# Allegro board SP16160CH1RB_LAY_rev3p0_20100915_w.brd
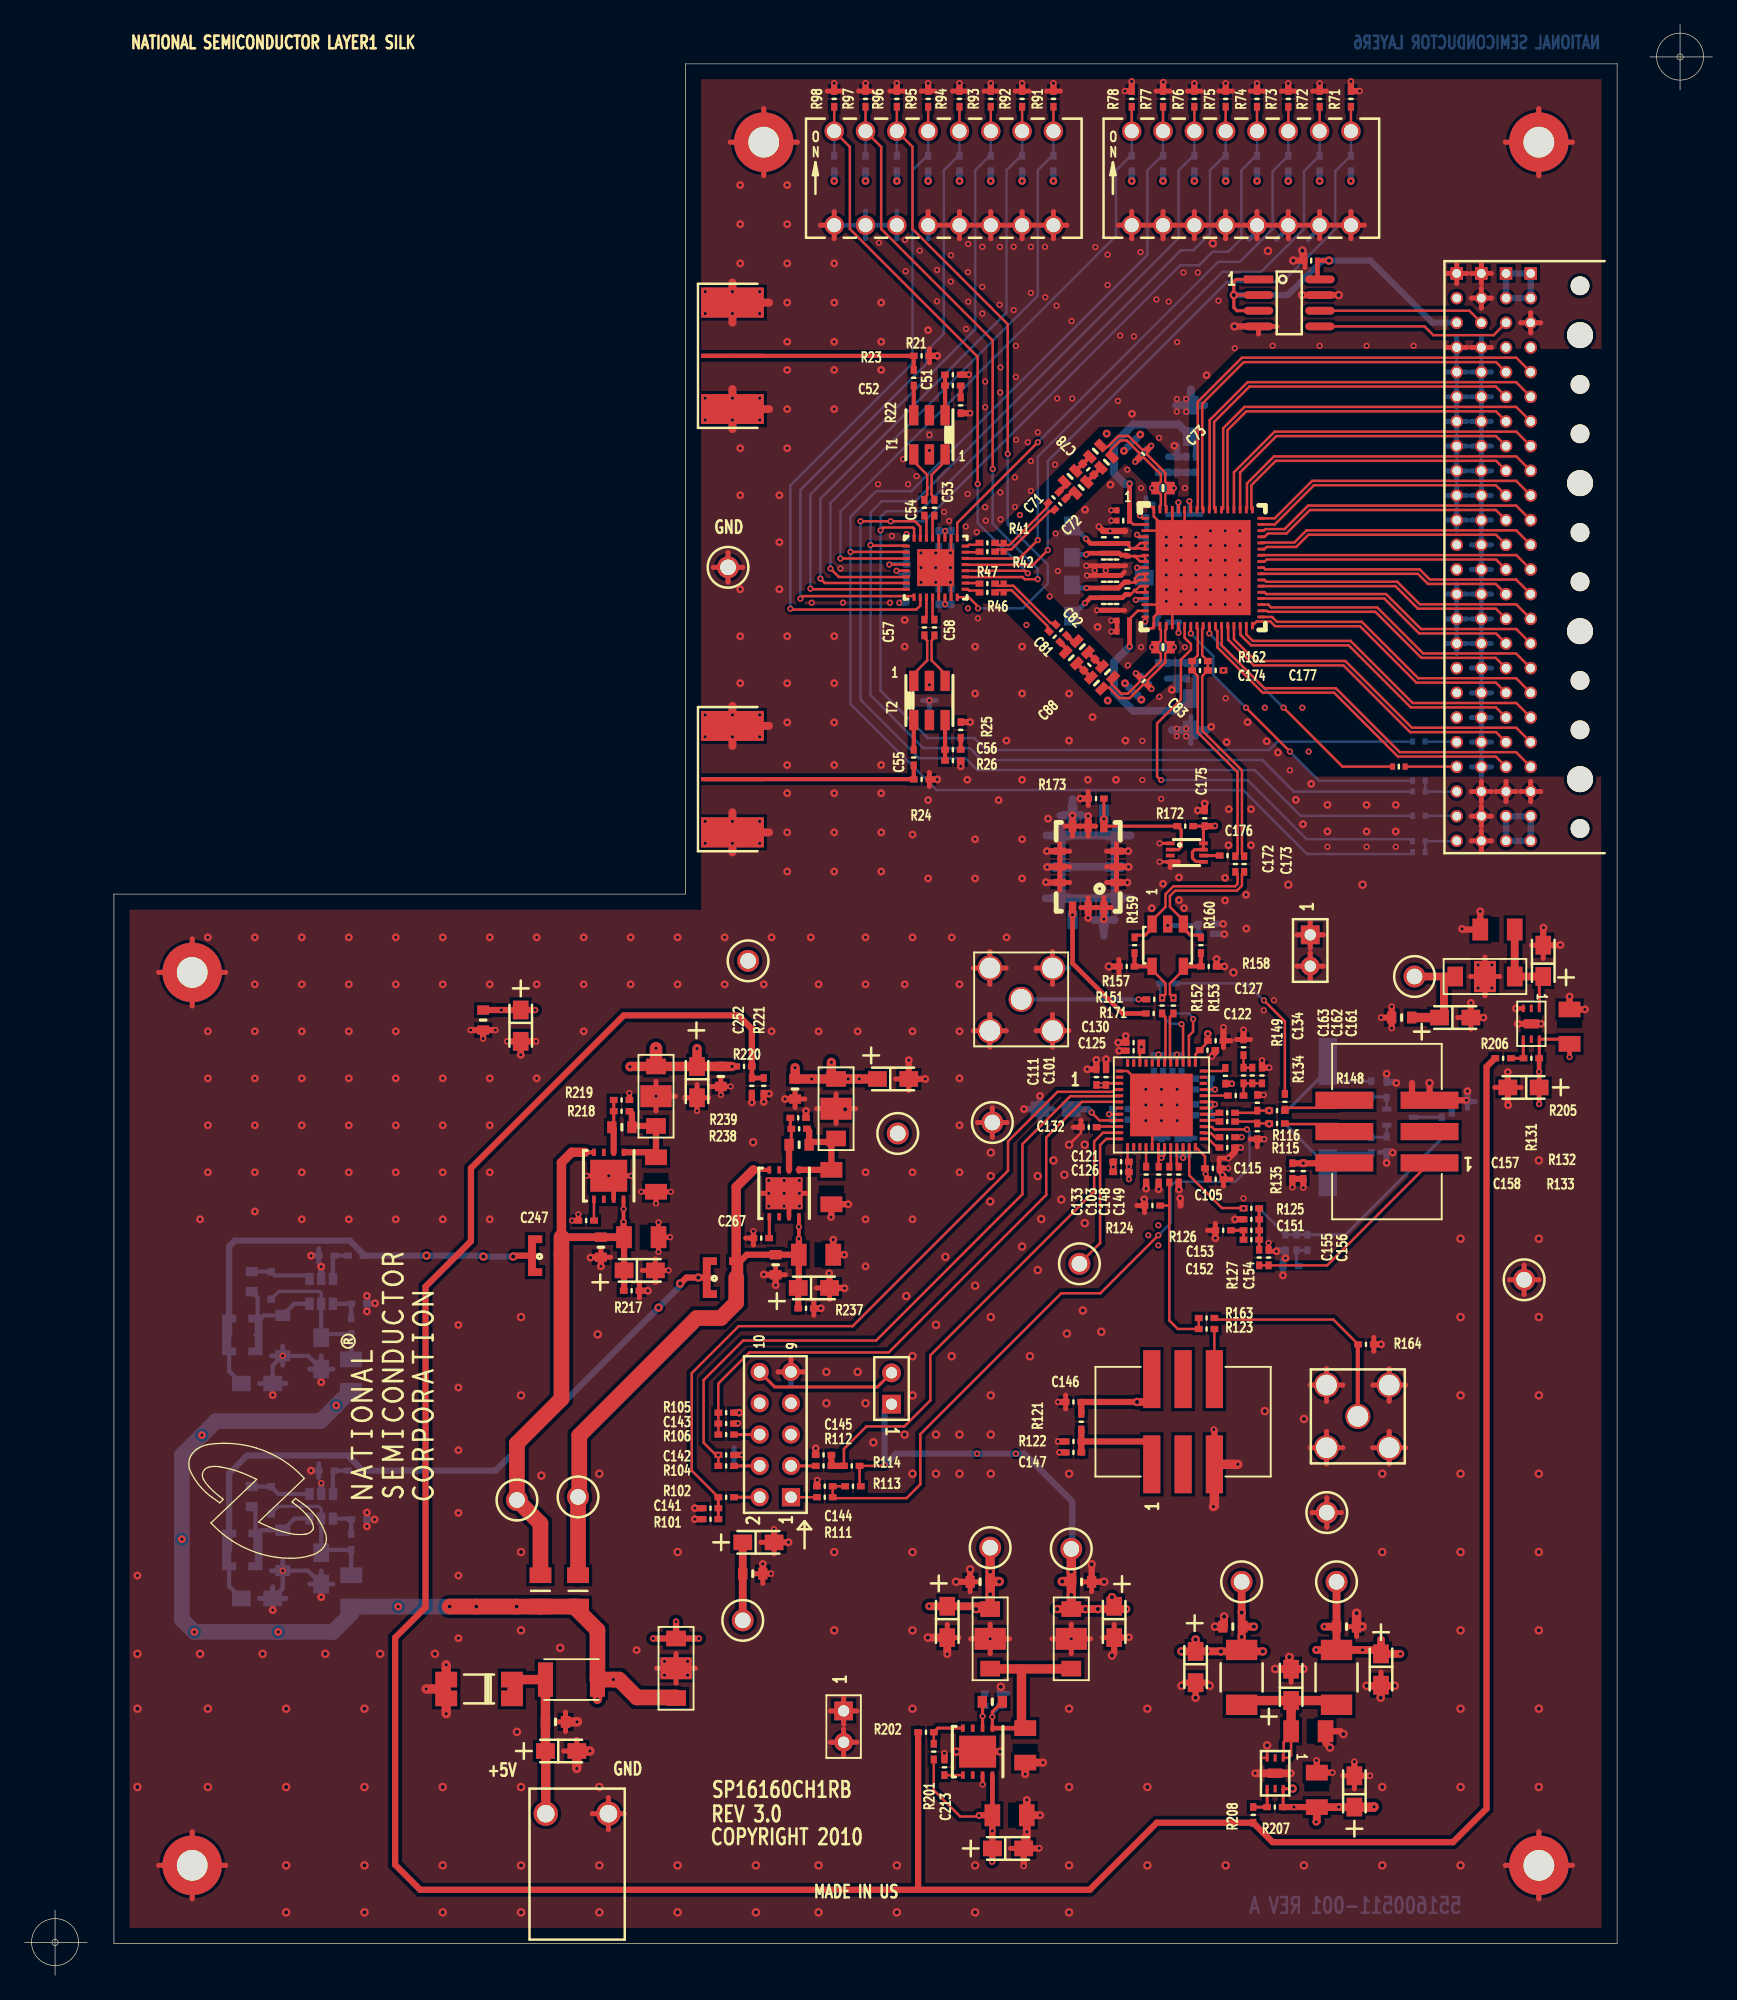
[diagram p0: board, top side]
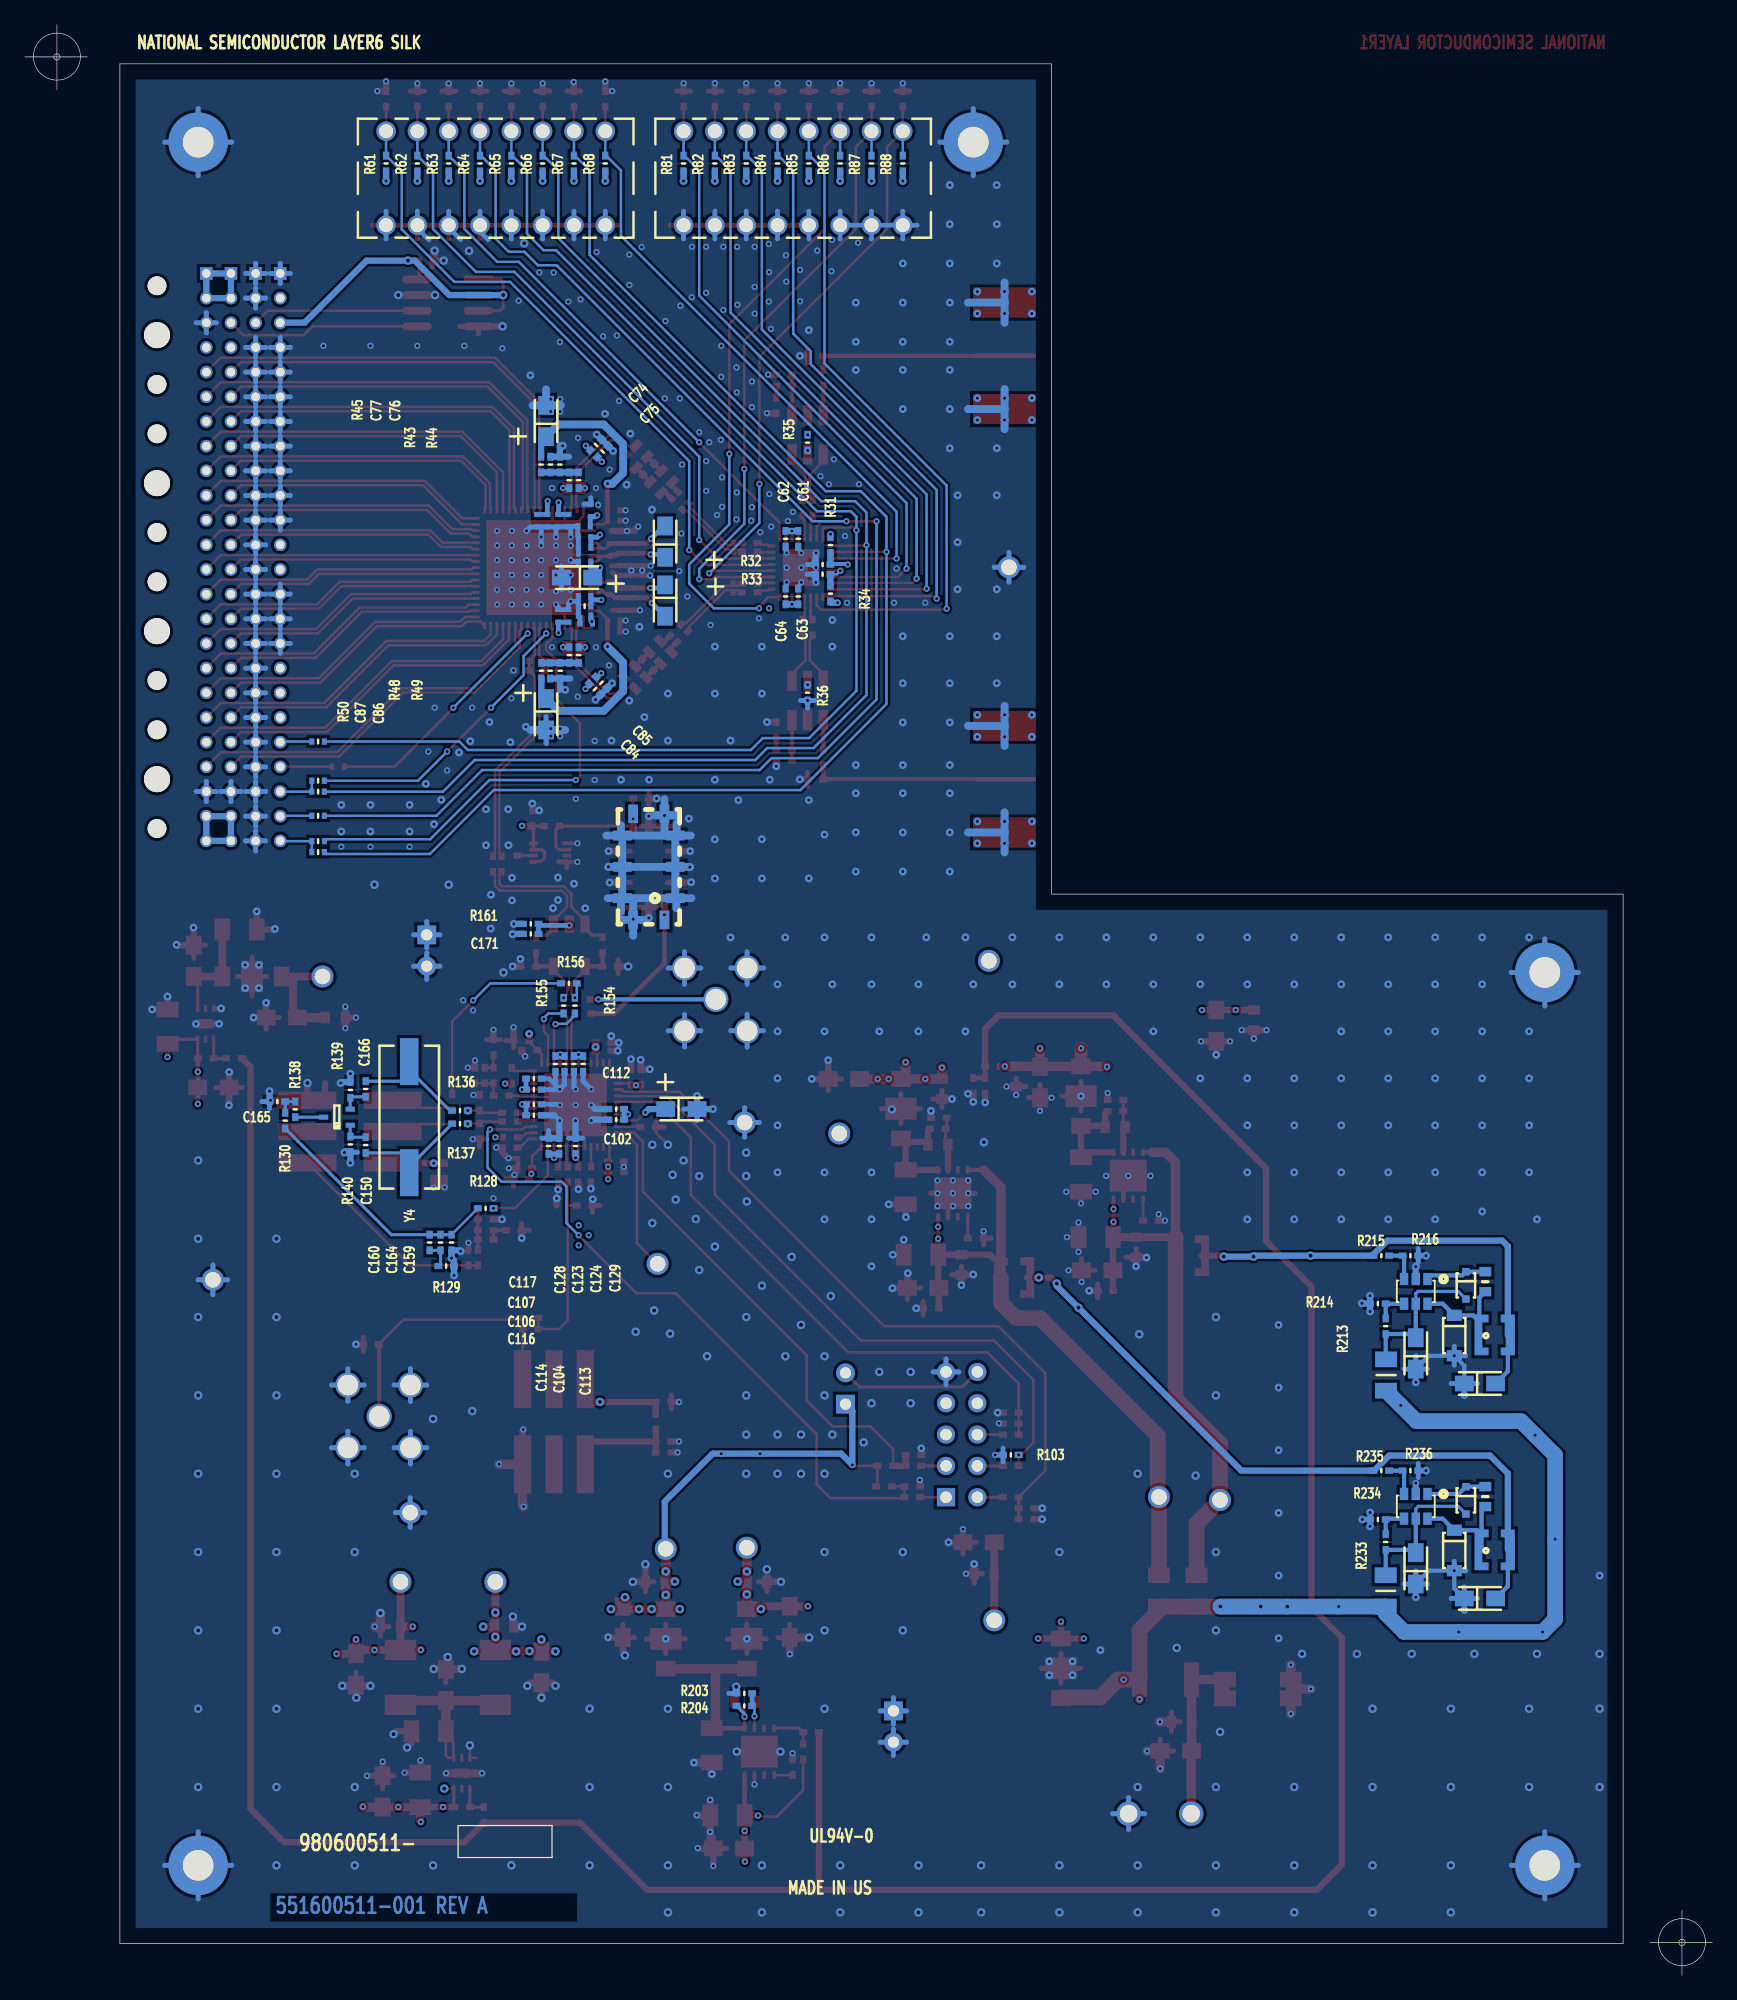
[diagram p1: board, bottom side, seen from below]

Outline 136.88 x 158.14 mm; copper layers: TOP, GROUND_L2, GROUND_L3, POWER_L4, GROUND_L5, BOTTOM. Coordinates in mm from the lower left corner of the outline.
Outline path: 7.24,87.66 53.59,87.66 53.59,154.97 129.16,154.97 129.16,2.57 7.24,2.57 7.24,87.66

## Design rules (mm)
net group DIFF_PAIRS: nets N17069969

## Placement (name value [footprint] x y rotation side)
C1  0.1u  [C0201_NO_SS]  90.04 115.37 90 top
C2  0.1u  [C0402_NO_SS#2]  89.43 115.57 90 top
C3  10u  [SMD_SIZE3216]  84.94 116.23 90 bottom
C4  0.1u  [C0402_NO_SS#2]  88.54 114.78 270 top
C5  0.1u  [C0402_NO_SS#2]  87.53 116.59 90 top
C6  0.1u  [C0402_NO_SS#2]  88.04 114.78 270 top
C7  0.1u  [C0402_NO_SS#2]  88.54 116.59 90 top
C8  0.1u  [C0402_NO_SS#2]  87.53 114.78 270 top
C9  0.1u  [C0402_NO_SS#2]  88.04 116.59 90 top
C11  0.1u  [C0201_NO_SS]  90.04 112.6 270 top
C12  0.1u  [C0402_NO_SS#2]  89.43 112.45 270 top
C13  10u  [SMD_SIZE3216]  84.94 111.46 270 bottom
C14  0.1u  [C0402_NO_SS#2]  88.54 112.98 90 top
C15  0.1u  [C0402_NO_SS#2]  88.54 111.18 270 top
C16  0.1u  [C0402_NO_SS#2]  87.53 112.98 90 top
C17  0.1u  [C0402_NO_SS#2]  88.04 111.18 270 top
C18  0.1u  [C0402_NO_SS#2]  88.04 112.98 90 top
C19  0.1u  [C0402_NO_SS#2]  87.53 111.18 270 top
C21  0.01u  [C0402_NO_SS#2]  91.47 116.59 0 bottom
C22  0.1u  [C0402_NO_SS#2]  91.47 115.75 0 bottom
C23  0.01u  [C0402_NO_SS#2]  90.96 118.77 90 bottom
C24  0.1u  [C0402_NO_SS#2]  91.52 117.47 0 bottom
C25  0.01u  [C0402_NO_SS#2]  91.47 111.81 180 bottom
C26  0.1u  [C0402_NO_SS#2]  91.47 111 180 bottom
C27  0.01u  [C0402_NO_SS#2]  91.47 110.24 180 bottom
C28  0.1u  [C0402_NO_SS#2]  91.34 109.6 180 bottom
C29  10u  [SMD_SIZE3216]  92.08 113.31 0 bottom
C30  0.1u  [C0402_NO_SS#2]  91.47 114.6 0 bottom
C31  0.01u  [C0402_NO_SS#2]  94.49 117.93 270 bottom
C32  0.1u  [C0402_NO_SS#2]  95.33 117.93 270 bottom
C33  0.01u  [C0402_NO_SS#2]  93.6 117.93 270 bottom
C34  0.1u  [C0402_NO_SS#2]  92.79 117.93 270 bottom
C35  0.01u  [C0402_NO_SS#2]  93.6 110.21 90 bottom
C36  0.1u  [C0402_NO_SS#2]  92.79 110.21 90 bottom
C39  0.1u  [C0402_NO_SS#2]  104.34 139.01 180 top
C41  0.1u  [C0402_NO_SS#2]  89.1 117.93 0 top
C42  0.1u  [C0402_NO_SS#2]  89.1 118.77 0 top
C43  10u  [SMD_SIZE3216]  94.59 126.01 90 bottom
C44  0.1u  [C0402_NO_SS#2]  89.1 109.83 0 top
C45  0.1u  [C0402_NO_SS#2]  89.1 108.94 0 top
C46  10u  [SMD_SIZE3216]  94.59 102.23 270 bottom
C51  0.1u  [SMD_SIZE0402]  72.11 129.51 270 top
C52  0.1u  [SMD_SIZE0402]  75.29 128.88 180 top
C53  0.1u  [SMD_SIZE0402]  73.79 118.97 270 top
C54  0.1u  [SMD_SIZE0402]  72.97 118.97 270 top
C55  0.1u  [SMD_SIZE0402]  72.11 98.73 90 top
C56  0.1u  [SMD_SIZE0402]  75.29 99.36 180 top
C57  0.1u  [SMD_SIZE0402]  72.97 109.27 90 top
C58  0.1u  [SMD_SIZE0402]  73.79 109.27 90 top
C61  0.1u  [SMD_SIZE0402]  74.14 116.46 270 bottom
C62  0.01u  [SMD_SIZE0402]  75.16 116.46 270 bottom
C63  0.1u  [SMD_SIZE0402]  74.14 111.79 90 bottom
C64  0.01u  [SMD_SIZE0402]  75.16 111.79 90 bottom
C71  0.1u  [SMD_SIZE0402]  83.44 119.81 45 top
C72  0.1u  [SMD_SIZE0402]  83.98 119.28 45 top
C73  16p  [SMD_SIZE0402]  90.72 123.35 225 top
C74  4p  [SMD_SIZE0402]  90.54 124.07 135 bottom
C75  4p  [SMD_SIZE0402]  90 123.53 315 bottom
C76  0.01u  [SMD_SIZE0402]  93.47 122.48 90 bottom
C77  0.1u  [SMD_SIZE0402]  94.23 122.48 90 bottom
C78  4p  [SMD_SIZE0402]  86.26 122.1 315 top
C79  3p  [C0402_NO_SS]  79.4 115.77 270 top
C80  3p  [C0402_NO_SS]  79.4 112.47 90 top
C81  0.1u  [SMD_SIZE0402]  83.53 108.52 315 top
C82  0.1u  [SMD_SIZE0402]  84.07 109.06 315 top
C83  16p  [SMD_SIZE0402]  90.76 104.93 135 top
C84  4p  [SMD_SIZE0402]  90.63 104.26 225 bottom
C85  4p  [SMD_SIZE0402]  90.09 104.8 45 bottom
C86  0.01u  [SMD_SIZE0402]  93.45 105.77 270 bottom
C87  0.1u  [SMD_SIZE0402]  94.26 105.77 270 bottom
C88  4p  [SMD_SIZE0402]  86.35 106.24 45 top
C101  100p  [SMD_SIZE0402]  87.71 72.82 270 top
C102  100p  [SMD_SIZE0402]  88.9 69.37 180 bottom
C103  100p  [SMD_SIZE0402]  91.97 64.92 90 top
C104  100p  [SMD_SIZE0402]  93.52 67.23 270 bottom
C105  100p  [SMD_SIZE0402]  96.6 64.54 180 top
C106  100p  [SMD_SIZE0402]  95.58 70.61 0 bottom
C107  100p  [SMD_SIZE0402]  95.58 71.81 0 bottom
C111  0.1u  [SMD_SIZE0402]  86.92 72.82 270 top
C112  0.1u  [SMD_SIZE0402]  88.9 70.23 180 bottom
C113  0.1u  [SMD_SIZE0402]  92.2 67.23 270 bottom
C114  0.1u  [SMD_SIZE0402]  94.39 67.23 270 bottom
C115  0.1u  [SMD_SIZE0402]  96.37 65.43 180 top
C116  0.1u  [SMD_SIZE0402]  95.58 69.72 0 bottom
C117  0.1u  [SMD_SIZE0402]  95.58 72.69 0 bottom
C121  100p  [SMD_SIZE0402]  88.93 65.96 0 top
C122  100p  [SMD_SIZE0402]  95.94 75.01 180 top
C123  100p  [SMD_SIZE0402]  93.09 73.89 90 bottom
C124  100p  [SMD_SIZE0402]  92.33 73.89 90 bottom
C125  100p  [SMD_SIZE0402]  89.94 74.96 0 top
C126  0.1u  [SMD_SIZE0402]  88.93 65.13 0 top
C127  0.1u  [SMD_SIZE0402]  96.6 75.77 180 top
C128  0.1u  [SMD_SIZE0402]  93.83 73.89 90 bottom
C129  0.1u  [SMD_SIZE0402]  91.59 73.89 90 bottom
C130  0.1u  [SMD_SIZE0402]  89.94 75.62 0 top
C131  10u  [SMD_SIZE3216]  83.62 70.23 180 bottom
C132  0.1u  [SMD_SIZE0402]  86.31 68.76 0 top
C133  1u  [SMD_SIZE0402]  90.96 64.92 90 top
C134  1u  [SMD_SIZE0402]  97.38 72.92 270 top
C141  A/R  [SMD_SIZE0402]  55.63 37.87 0 top
C142  A/R  [SMD_SIZE0402]  56.9 42.19 180 top
C143  A/R  [SMD_SIZE0402]  56.9 44.73 180 top
C144  100p  [SMD_SIZE0402]  64.9 39.65 0 top
C145  0.1u  [SMD_SIZE0402]  64.8 42.19 0 top
C146  0.01u  [SMD_SIZE0402]  85.06 46.48 0 top
C147  A/R  [SMD_SIZE0402]  85.06 42.39 0 top
C148  0.1u  [SMD_SIZE0402]  92.84 64.92 90 top
C149  0.1u  [SMD_SIZE0402]  93.6 64.92 90 top
C150  A/R  [SMD_SIZE0402]  109.22 67.31 270 bottom
C151  0.1u  [SMD_SIZE0402]  99.49 61.29 0 top
C152  0.68u  [SMD_SIZE0402]  99.49 59.64 0 top
C153  A/R  [SMD_SIZE0402]  99.49 60.4 0 top
C154  A/R  [SMD_SIZE0402]  100.89 58.19 270 top
C155  0.1u  [SMD_SIZE0402]  102.82 65.2 90 top
C156  100p  [SMD_SIZE0402]  103.71 65.2 90 top
C157  0.1u  [SMD_SIZE0402]  97.54 69.93 0 top
C158  0.1u  [SMD_SIZE0402]  97.54 69.22 0 top
C159  A/R  [SMD_SIZE0402]  102.26 59.41 90 bottom
C160  A/R  [SMD_SIZE0402]  104.04 59.41 90 bottom
C161  A/R  [SMD_SIZE0402]  100.36 72.95 270 top
C162  A/R  [SMD_SIZE0402]  99.57 72.95 270 top
C163  12n  [SMD_SIZE0402]  98.86 72.95 270 top
C164  A/R  [SMD_SIZE0402]  103.15 59.41 90 bottom
C165  A/R  [SMD_SIZE0402]  116.38 70.84 180 bottom
C166  A/R  [SMD_SIZE0402]  109.22 71.86 90 bottom
C171  A/R  [SMD_SIZE0402]  95.83 84.43 180 bottom
C172  A/R  [SMD_SIZE0402]  98.2 90.09 270 top
C173  A/R  [SMD_SIZE0402]  98.91 90.09 270 top
C174  10p  [SMD_SIZE0402]  95.33 105.79 0 top
C175  0.1u  [SMD_SIZE0402]  95.71 93.8 90 top
C176  20p  [SMD_SIZE0402]  97.56 90.78 180 top
C177  0.1u  [SMD_SIZE0402]  96.6 105.79 0 top
C201  10u  [SMD_SIZE3216]  43.51 18.19 0 top
C202  0.1u  [SMD_SIZE0603]  43.05 20.55 0 top
C203  10u  [SMD_SIZE3216]  40.23 76.99 270 top
C204  0.1u  [SMD_SIZE0603]  37.19 77.44 270 top
C205  10u  [SMD_SIZE3216]  59.51 35.1 0 top
C206  0.1u  [SMD_SIZE0603]  59.05 32.56 0 top
C211  10u  [SMD_SIZE3216]  79.76 10.29 0 top
C212  1u  [SMD_SIZE1206]  78.87 12.98 0 top
C213  0.01u  [SMD_SIZE0402]  74.6 16.87 90 top
C214  2.2n  [SMD_SIZE0603]  78.49 22.17 180 top
C215  10u  [SMD_SIZE1206]  81.15 19.66 270 top
C216  10u  [SMD_SIZE3216]  88.37 28.65 270 top
C217  0.1u  [SMD_SIZE0603]  85.73 31.9 0 top
C218  10u  [SMD_SIZE3216]  74.83 28.65 270 top
C219  0.1u  [SMD_SIZE0603]  77.5 31.9 180 top
C221  10u  [SMD_SIZE3216]  121.56 71.98 180 top
C222  1u  [SMD_SIZE1206]  125.3 75.9 90 top
C223  10u  [SMD_SIZE3216]  123.16 82.25 90 top
C224  1u  [SMD_SIZE1206]  120.47 84.79 180 top
C225  10u  [SMD_SIZE3216]  116.03 77.65 0 top
C226  0.1u  [SMD_SIZE0603]  111.68 77.65 180 top
C231  10u  [SMD_SIZE3216]  107.85 14.91 90 top
C232  1u  [SMD_SIZE1206]  104.8 14.02 90 top
C233  10u  [SMD_SIZE3216]  102.72 23.55 90 top
C234  1u  [SMD_SIZE1206]  103.1 19.79 0 top
C235  10u  [SMD_SIZE3216]  94.97 24.99 270 top
C236  0.1u  [SMD_SIZE0603]  97.99 28.27 180 top
C237  10u  [SMD_SIZE3216]  110.01 24.79 270 top
C238  0.1u  [SMD_SIZE0603]  107.21 28.27 0 top
C241  10u  [SMD_SIZE3216]  24.05 50.42 90 bottom
C242  0.01u  [SMD_SIZE0603]  18.41 56.24 270 bottom
C243  10u  [SMD_SIZE3216]  18.85 47.98 180 bottom
C244  A/R  [SMD_SIZE0603]  46.74 59.03 90 top
C245  10u  [SMD_SIZE3216]  49.89 57.15 0 top
C246  1u  [SMD_SIZE1206]  49 59.84 0 top
C247  0.01u  [SMD_SIZE0402]  45.54 61.19 180 top
C248  2.2n  [SMD_SIZE0603]  48.44 68.76 180 top
C249  10u  [SMD_SIZE1206]  51.21 65.94 270 top
C250  10u  [SMD_SIZE3216]  54.53 72.42 270 top
C251  0.1u  [SMD_SIZE0603]  56.46 72.87 270 top
C252  0.1u  [SMD_SIZE0402]  58.98 72.11 270 top
C261  10u  [SMD_SIZE3216]  24.05 32.99 90 bottom
C262  0.01u  [SMD_SIZE0603]  18.41 38.81 270 bottom
C263  10u  [SMD_SIZE3216]  18.85 30.56 180 bottom
C264  A/R  [SMD_SIZE0603]  60.91 57.61 90 top
C265  10u  [SMD_SIZE3216]  64.01 55.73 0 top
C266  1u  [SMD_SIZE1206]  63.17 58.42 0 top
C267  0.01u  [SMD_SIZE0402]  59.74 59.77 180 top
C268  2.2n  [SMD_SIZE0603]  62.81 67.34 180 top
C269  10u  [SMD_SIZE1206]  65.43 64.92 270 top
C270  10u  [SMD_SIZE3216]  70.43 72.67 0 top
C271  0.1u  [SMD_SIZE0603]  62.48 71.86 270 top
D1  1N5818M  [MELF-MLL41]  36.86 23.22 180 top
D2  BAT54WS  [SOD323]  19.99 55.93 270 bottom
D3  MBR0530  [SOD_123]  20.93 51.87 270 bottom
D4  BAT54WS  [SOD323]  19.99 38.51 270 bottom
D5  MBR0530  [SOD_123]  20.93 34.44 270 bottom
D6  SMV1249-074  [SC70_3]  111.56 69.57 0 bottom
H3  HDR2x5  [BLKCON_5X2]  60.88 43.84 180 top
H4  4 - 6x4 FutureBus Connector  [FBUS_RS_96_ECL]  122.15 137.97 0 top
JP1  HDR-1x2  [BLKCON_2X1]  70.31 47.57 180 top
JP10  HDR-1x2  [BLKCON_2X1]  66.42 20.17 0 top
JP11  HDR-1x2  [BLKCON_2X1]  104.27 83.08 0 top
L1  110n  [0603CS]  84.79 121.52 45 top
L2  110n  [0603CS]  85.69 120.62 45 top
L3  33n  [0603CS]  92.33 120.57 0 top
L4  110n  [0603CS]  84.88 106.81 315 top
L5  110n  [0603CS]  85.78 107.71 315 top
L6  33n  [0603CS]  92.33 107.67 0 top
L7  200n  [0603CS]  87.74 122.67 45 top
L8  200n  [0603CS]  87.83 105.66 315 top
L9  200n  [0603CS]  86.93 104.77 315 top
L10  200n  [0603CS]  86.84 123.57 45 top
L11  EXC-CL4532U1  [L4532]  44.35 23.98 0 top
L12  100u  [SMD_SIZE1812R]  98.7 24.16 90 top
L13  100u  [SMD_SIZE1812R]  106.4 24.16 90 top
L21  4.6u  [LPS3008_472ML]  17.65 50.27 180 bottom
L22  0 ohm  [LPS3008_472ML]  42.47 56.69 0 top
L23  4.6u  [LPS3008_472ML]  17.65 32.84 180 bottom
L24  0 ohm  [LPS3008_472ML]  56.64 54.91 0 top
MH1  M-Hole  [MOUNTING_HOLE]  59.94 148.62 0 top
MH2  M-Hole  [MOUNTING_HOLE]  122.81 148.62 0 top
MH3  M-Hole  [MOUNTING_HOLE]  13.59 8.92 0 top
MH4  M-Hole  [MOUNTING_HOLE]  122.81 8.92 0 top
MH5  M-Hole  [MOUNTING_HOLE]  13.59 81.31 0 top
NOREF  -  []  -131.22 -104.9 0 top
NOREF#2  -  []  -2.62 2.64 0 top
NOREF#3  -  []  -29.59 -126.97 0 top
NOREF#4  -  []  220.14 -17.25 0 top
NOREF#5  -  []  129.18 155.5 0 top
NOREF#6  -  []  15.49 46.86 90 top
NOREF#7  -  []  53.59 87.66 90 top
NOREF#8  -  []  7.24 2.57 90 top
NOREF#9  -  []  7.24 2.57 0 top
POWER  Terminal_Block2  [MSTBA_RA_200_2]  44.81 13.11 90 top
R1  10  [C0402_NO_SS#2]  111.46 97.99 0 top
R2  10  [C0402_NO_SS#2]  113.08 96.85 0 bottom
R3  10  [C0402_NO_SS#2]  113.08 91.95 0 bottom
R4  10  [C0402_NO_SS#2]  113.08 91.06 0 bottom
R5  10  [C0402_NO_SS#2]  113.08 95.96 0 bottom
R6  A/R  [C0402_NO_SS#2]  113.08 94.01 0 bottom
R7  10  [C0402_NO_SS#2]  113.08 100.03 0 bottom
R21  A/R  [SMD_SIZE0402]  72.75 131.29 0 top
R22  0  [SMD_SIZE0402]  75.92 127.28 270 top
R23  A/R  [SMD_SIZE0402]  75.29 129.77 0 top
R24  A/R  [SMD_SIZE0402]  72.75 96.95 0 top
R25  0  [SMD_SIZE0402]  75.92 100.97 90 top
R26  A/R  [SMD_SIZE0402]  75.29 98.48 0 top
R31  A/R  [SMD_SIZE0402]  71.53 115.95 90 bottom
R32  0  [SMD_SIZE0402]  72.16 114.38 0 bottom
R33  24k  [SMD_SIZE0402]  72.16 113.59 0 bottom
R34  11k  [SMD_SIZE0402]  71.53 112.01 270 bottom
R35  0  [SMD_SIZE0402]  73.38 124.26 90 bottom
R36  0  [SMD_SIZE0402]  73.38 103.99 270 bottom
R41  10  [SMD_SIZE0402]  78.08 116.13 0 top
R42  10  [SMD_SIZE0402]  78.08 115.42 0 top
R43  100  [SMD_SIZE0402]  92.71 121.21 90 bottom
R44  100  [SMD_SIZE0402]  91.95 121.21 270 bottom
R45  24.9  [SMD_SIZE0402]  95 122.48 90 bottom
R46  10  [SMD_SIZE0402]  78.08 112.12 0 top
R47  10  [SMD_SIZE0402]  78.08 112.83 0 top
R48  100  [SMD_SIZE0402]  92.71 107.04 270 bottom
R49  100  [SMD_SIZE0402]  91.95 107.04 90 bottom
R50  24.9  [SMD_SIZE0402]  94.97 105.77 270 bottom
R61  A/R  [SMD_SIZE0402]  107.57 146.89 90 bottom
R62  A/R  [SMD_SIZE0402]  105.03 146.89 90 bottom
R63  A/R  [SMD_SIZE0402]  102.49 146.89 90 bottom
R64  A/R  [SMD_SIZE0402]  99.95 146.89 90 bottom
R65  A/R  [SMD_SIZE0402]  97.41 146.89 90 bottom
R66  A/R  [SMD_SIZE0402]  94.87 146.89 90 bottom
R67  A/R  [SMD_SIZE0402]  92.33 146.89 90 bottom
R68  A/R  [SMD_SIZE0402]  89.79 146.89 90 bottom
R71  0  [SMD_SIZE0402]  107.57 152.12 90 top
R72  A/R  [SMD_SIZE0402]  105.03 152.12 90 top
R73  0  [SMD_SIZE0402]  102.49 152.12 90 top
R74  A/R  [SMD_SIZE0402]  99.95 152.12 90 top
R75  A/R  [SMD_SIZE0402]  97.41 152.12 90 top
R76  A/R  [SMD_SIZE0402]  94.87 152.12 90 top
R77  A/R  [SMD_SIZE0402]  92.33 152.12 90 top
R78  0  [SMD_SIZE0402]  89.79 152.12 90 top
R81  A/R  [SMD_SIZE0402]  83.44 146.89 90 bottom
R82  A/R  [SMD_SIZE0402]  80.9 146.89 90 bottom
R83  A/R  [SMD_SIZE0402]  78.36 146.89 90 bottom
R84  A/R  [SMD_SIZE0402]  75.82 146.89 90 bottom
R85  A/R  [SMD_SIZE0402]  73.28 146.89 90 bottom
R86  A/R  [SMD_SIZE0402]  70.74 146.89 90 bottom
R87  A/R  [SMD_SIZE0402]  68.2 146.89 90 bottom
R88  A/R  [SMD_SIZE0402]  65.66 146.89 90 bottom
R91  0  [SMD_SIZE0402]  83.44 152.12 90 top
R92  0  [SMD_SIZE0402]  80.9 152.12 90 top
R93  0  [SMD_SIZE0402]  78.36 152.12 90 top
R94  0  [SMD_SIZE0402]  75.82 152.12 90 top
R95  0  [SMD_SIZE0402]  73.28 152.12 90 top
R96  0  [SMD_SIZE0402]  70.74 152.12 90 top
R97  A/R  [SMD_SIZE0402]  68.2 152.12 90 top
R98  0  [SMD_SIZE0402]  65.66 152.12 90 top
R101  24k  [SMD_SIZE0402]  55.63 36.98 180 top
R102  11k  [SMD_SIZE0402]  56.9 38.76 0 top
R103  24k  [SMD_SIZE0402]  56.9 42.19 0 bottom
R104  11k  [SMD_SIZE0402]  56.9 41.3 0 top
R105  24k  [SMD_SIZE0402]  56.9 45.62 0 top
R106  11k  [SMD_SIZE0402]  56.9 43.84 0 top
R111  200  [SMD_SIZE0402]  64.9 38.76 180 top
R112  200  [SMD_SIZE0402]  64.8 41.3 180 top
R113  2.32k  [SMD_SIZE0402]  67.18 39.65 0 top
R114  2.32k  [SMD_SIZE0402]  67.08 41.3 0 top
R115  0  [SMD_SIZE0402]  97.54 67.11 180 top
R116  0  [SMD_SIZE0402]  97.54 67.94 180 top
R121  1k  [SMD_SIZE0402]  85.7 44.88 90 top
R122  A/R  [SMD_SIZE0402]  85.06 43.28 0 top
R123  200  [SMD_SIZE0402]  95.86 52.4 180 top
R124  200  [SMD_SIZE0402]  91.47 62.41 180 top
R125  0  [SMD_SIZE0402]  99.49 62.18 0 top
R126  39k  [SMD_SIZE0402]  97.21 60.4 0 top
R127  0  [SMD_SIZE0402]  100.13 58.19 270 top
R128  A/R  [SMD_SIZE0402]  99.49 62.18 0 bottom
R129  A/R  [SMD_SIZE0402]  102.69 57.51 0 bottom
R130  A/R  [SMD_SIZE0402]  115.75 69.29 90 bottom
R131  A/R  [SMD_SIZE0402]  102.21 70.82 90 top
R132  200  [SMD_SIZE0402]  101.57 70.1 0 top
R133  A/R  [SMD_SIZE0402]  101.57 69.06 0 top
R134  200  [SMD_SIZE0402]  99.97 70.74 90 top
R135  0  [SMD_SIZE0402]  99.97 68.43 90 top
R136  A/R  [SMD_SIZE0402]  101.57 70.1 180 bottom
R137  A/R  [SMD_SIZE0402]  101.57 69.04 180 bottom
R138  A/R  [SMD_SIZE0402]  114.94 70.21 90 bottom
R139  A/R  [SMD_SIZE0402]  110.46 71.78 270 bottom
R140  A/R  [SMD_SIZE0402]  110.46 67.36 270 bottom
R148  0  [SMD_SIZE0402]  98.22 71.32 0 top
R149  1.8k  [SMD_SIZE0402]  98.86 75.23 270 top
R151  A/R  [SMD_SIZE0402]  91.62 79.12 180 top
R152  A/R  [SMD_SIZE0402]  92.25 78.61 270 top
R153  A/R  [SMD_SIZE0402]  93.17 78.61 270 top
R154  A/R  [SMD_SIZE0402]  92.25 78.61 270 bottom
R155  A/R  [SMD_SIZE0402]  93.17 78.61 270 bottom
R156  A/R  [SMD_SIZE0402]  92.74 80.42 180 bottom
R157  A/R  [SMD_SIZE0402]  89.38 81.79 180 top
R158  A/R  [SMD_SIZE0402]  96.04 81.79 180 top
R159  A/R  [SMD_SIZE0402]  90.02 83.52 90 top
R160  A/R  [SMD_SIZE0402]  95.4 83.52 90 top
R161  A/R  [SMD_SIZE0402]  95.83 85.24 180 bottom
R162  A/R  [SMD_SIZE0402]  95.33 106.55 180 top
R163  A/R  [SMD_SIZE0402]  95.86 53.29 180 top
R164  A/R  [SMD_SIZE0402]  108.79 51.16 180 top
R171  49.9  [SMD_SIZE0402]  91.57 77.98 0 top
R172  402  [SMD_SIZE0402]  94.13 93.17 180 top
R173  402  [SMD_SIZE0402]  86.89 95.4 180 top
R201  A/R  [SMD_SIZE0402]  73.74 18.14 90 top
R202  0  [SMD_SIZE0402]  73.1 19.71 0 top
R203  1k  [SMD_SIZE0402]  78.51 22.86 0 bottom
R204  2.32k  [SMD_SIZE0402]  78.51 21.84 0 bottom
R205  A/R  [SMD_SIZE0402]  122.2 74.35 180 top
R206  0  [SMD_SIZE0402]  119.91 74.35 0 top
R207  A/R  [SMD_SIZE0402]  101.4 13.64 180 top
R208  0  [SMD_SIZE0402]  99.64 13 90 top
R211  A/R  [SMD_SIZE0805]  41.83 31.17 90 top
R212  0  [SMD_SIZE0805]  26.47 48.67 90 bottom
R213  100k  [SMD_SIZE0402]  26.49 52.63 90 bottom
R214  A/R  [SMD_SIZE0402]  27.13 54.46 180 bottom
R215  39k  [SMD_SIZE0402]  26.85 58.34 180 bottom
R216  11k  [SMD_SIZE0402]  24.49 58.34 180 bottom
R217  A/R  [SMD_SIZE0402]  49.23 55.5 180 top
R218  2k  [SMD_SIZE0402]  48.41 70.05 0 top
R219  1k  [SMD_SIZE0402]  48.41 70.97 0 top
R220  11k  [SMD_SIZE0402]  58.34 73.69 180 top
R221  24k  [SMD_SIZE0402]  59.94 72.11 90 top
R231  A/R  [SMD_SIZE0805]  44.88 31.17 90 top
R232  0  [SMD_SIZE0805]  26.49 31.17 90 bottom
R233  100k  [SMD_SIZE0402]  26.49 35.13 90 bottom
R234  A/R  [SMD_SIZE0402]  27.13 36.96 180 bottom
R235  24k  [SMD_SIZE0402]  26.85 40.92 180 bottom
R236  11k  [SMD_SIZE0402]  24.49 40.92 180 bottom
R237  A/R  [SMD_SIZE0402]  63.37 54.08 180 top
R238  806  [SMD_SIZE0402]  62.81 68.63 0 top
R239  1k  [SMD_SIZE0402]  62.74 69.52 0 top
SAM_AMP_Q  WM5534  [RF_SMA_END_LAUNCH]  57.4 96.98 0 top
SMA_AMP_I  WM5534  [RF_SMA_END_LAUNCH]  57.4 131.29 0 top
SMA_CLK  A/R  [SMA_V_CLR]  80.82 79.12 0 top
SMA_REF  A/R  [SMA_V_CLR]  108.13 45.31 0 top
SWGI  A/R  [BD08]  91.06 145.69 0 top
SWGQ  A/R  [BD08]  66.93 145.69 0 top
T1  TCM4-19+  [DB714]  73.38 124.89 180 top
T2  TCM4-19+  [DB714]  73.38 103.35 0 top
T4  A/R  [SM_SOT23_5_WGP150]  92.71 83.52 90 top
TP1  GND  [TP_500X_50]  121.62 56.39 0 top
TP2  GND  [TP_500X_50]  57.05 114.15 0 top
TP3  GND  [TP_500X_50]  78.49 69.14 0 top
TP4  GND  [TP_500X_50]  105.61 37.52 0 top
TP5  LD  [TP_500X_50]  85.55 57.68 0 top
TP11  VAMP  [TP_500X_50]  58.24 28.78 180 top
TP12  VPLL  [TP_500X_50]  84.89 34.57 0 top
TP13  VPLLIO  [TP_500X_50]  78.31 34.67 0 top
TP14  VA3P0SW  [TP_500X_50]  39.93 38.53 0 top
TP15  VA3P0  [TP_500X_50]  58.67 82.25 0 top
TP16  VA1P8SW  [TP_500X_50]  44.88 38.79 0 top
TP17  VA1P8  [TP_500X_50]  70.82 68.25 0 top
TP18  VIO1p8  [TP_500X_50]  112.73 80.98 0 top
TP19  VREFOSC  [TP_500X_50]  98.7 31.9 0 top
TP20  VVCXO  [TP_500X_50]  106.4 31.9 0 top
U1  ADC16DV160  [SC-MKT-LQA68A]  95.58 114.12 0 top
U2  24C02/SO8  [SOIC8_050_WG244_L200]  102.57 135.59 0 top
U3  LMH6517  [32LLP_SQA32A]  73.89 114.12 0 top
U4  LMK04021  [LLP48_P5M_7X7_EP]  92.2 70.56 0 top
U5  TSF153F  [TFS153F]  86.26 89.87 90 top
U6  NC7WV125  [NC7WV125_8P]  92.91 91.77 0 top
U11  LM3878SD-ADJ  [SC-MKT-SDC08A_LLP]  77.29 18.14 90 top
U12  LM2734Y  [TSOT-6]  24.05 55.45 270 bottom
U13  LP3878SD-ADJ  [SC-MKT-SDC08A_LLP]  47.37 64.82 90 top
U14  LM2734Y  [TSOT-6]  24.05 38.02 270 bottom
U15  LP3878SD-ADJ  [SC-MKT-SDC08A_LLP]  61.59 63.4 90 top
U16  LP5900SD-1.8  [LLP6_65M_WG2P5_L2P2_EP]  122.2 77.14 270 top
U17  LP5900SD-3.3  [LLP6_65M_WG2P5_L2P2_EP]  101.42 16.38 270 top
U18  TFS 123A  [TFS123A]  86.26 89.87 90 bottom
Y2  OSC 76.8MHz CVHD-950-76.800  [SOIC6_100_WG272_L560]  110.49 68.4 180 top
Y3  OSC 61.44MHz CCHD-950-25-61.440  [SOIC6_100_WG272_L560]  93.95 44.88 90 top
Y4  VXB1-1127-12M288  [VXB1_1127_12M288]  105.69 69.57 270 bottom
Z1  NFM41PC204F1H3  [NFM41P]  52.83 24.89 90 top
Z2  NFM41PC204F1H3  [NFM41P]  84.89 27.28 90 top
Z3  NFM41PC204F1H3  [NFM41P]  78.31 27.28 90 top
Z4  NFM41PC204F1H3  [NFM41P]  51.21 71.27 90 top
Z5  NFM41PC204F1H3  [NFM41P]  65.81 70.26 90 top
Z6  NFM41PC204F1H3  [NFM41P]  118.44 80.98 180 top

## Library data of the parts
C1 C2 C4-C7 C11 C12 C14-C17 C214 C241-C244 C248 C261-C264 C268 = Capacitor_3
C3 C13 C29 C43 C46 C131 C201 C203 C205 C211 C216 C218 C221 C223 C225 C231 C233 C235 C237 C245 C250 C265 C270 = Cap_Polar_1
C8 C9 C18 C19 C41 C42 C44 C45 C51-C58 C71-C88 C101-C107 C111-C117 C121-C130 C132-C134 C141-C166 C171-C177 C202 C204 C206 C212 C213 C215 C217 C219 C222 C224 C226 C232 C234 C236 C238 C246 C247 C249 C251 C252 C266 C267 C269 C271 = Capacitor_0
C21-C28 C30-C36 C39 C61-C64 = Cap_4
D1 = 1N5818M_0
D2 D4 = D1N4148/27C_0
D3 D5 = MLL4728_0
D6 = SMV1249-074_2
H3 = HDR-2x5
H4 = CON-96pin-FB-adc14156_12
JP1 JP10 JP11 = HDR-1x2_0
L1-L10 L12 L13 = Inductor_0
L11 L21-L24 = EXC-CL4532U1
MH1-MH5 = M-Hole
POWER = Terminal_Block4_30
R1-R7 R21-R26 R31-R36 R41-R50 R61-R68 R71-R78 R81-R88 R91-R98 R101-R106 R111-R116 R121-R140 R148 R149 R151-R164 R171-R173 R201-R208 R211-R221 R231-R239 = Resistor_0
SAM_AMP_Q SMA_AMP_I SMA_CLK SMA_REF = SMA_CONN_2
SWGI SWGQ = DIP_SWITCH_8POS
T1 T2 = TCM4-19+_0
T4 = ETC1-1-13
TP1-TP4 = TestPoint_0
TP5 TP11-TP20 = HDR-1x1_0
U1 = ADC16130_LLP_2
U2 = 24C02/SO8_1
U3 = LMH6517_4
U4 = LMK04021_2
U5 = SAW_2
U6 = NC7WV125
U11 U13 U15 = LP3878MR-ADJ_1
U12 U14 = LM2734
U16 U17 = LP5900SD-3_0.3
U18 = TFS 123A
Y2 Y3 = CVPD-920-100_0.000
Y4 = VXB1-1127-12M288
Z1-Z6 = NFM41_0

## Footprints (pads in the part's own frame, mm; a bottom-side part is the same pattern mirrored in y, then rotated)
32LLP_SQA32A
  rect 0.599x0.249 smd: 1(-2.4,1.75) 2(-2.4,1.25) 3(-2.4,0.75) 4(-2.4,0.25) 5(-2.4,-0.25) 6(-2.4,-0.75) 7(-2.4,-1.25) 8(-2.4,-1.75) 17(2.4,-1.75) 18(2.4,-1.25) 19(2.4,-0.75) 20(2.4,-0.25) 21(2.4,0.25) 22(2.4,0.75) 23(2.4,1.25) 24(2.4,1.75)
  rect 0.249x0.599 smd: 9(-1.75,-2.4) 10(-1.25,-2.4) 11(-0.75,-2.4) 12(-0.25,-2.4) 13(0.25,-2.4) 14(0.75,-2.4) 15(1.25,-2.4) 16(1.75,-2.4) 25(1.75,2.4) 26(1.25,2.4) 27(0.75,2.4) 28(0.25,2.4) 29(-0.25,2.4) 30(-0.75,2.4) 31(-1.25,2.4) 32(-1.75,2.4)
  rect 3x3 smd: DAP(0,0)
0603CS
  rect 0.635x1.016 smd: 1(-0.635,0) 2(0.635,0)
BD08
  round 1.575 hole 1.143: 1(-1.27,-3.81) 2(-1.27,3.81) 3(1.27,-3.81) 4(1.27,3.81) 5(3.81,-3.81) 6(3.81,3.81) 7(6.35,-3.81) 8(6.35,3.81) 9(8.89,-3.81) 10(8.89,3.81) 11(11.43,-3.81) 12(11.43,3.81) 13(13.97,-3.81) 14(13.97,3.81) 15(16.51,-3.81) 16(16.51,3.81)
BLKCON_2X1
  rect 1.524x1.524 hole 0.914: 1(0,1.27)
  round 1.524 hole 0.914: 2(0,-1.27)
BLKCON_5X2
  rect 1.473x1.473 hole 0.94: 1(-1.27,5.08)
  round 1.473 hole 0.94: 2(1.27,5.08) 3(-1.27,2.54) 4(1.27,2.54) 5(-1.27,0) 6(1.27,0) 7(-1.27,-2.54) 8(1.27,-2.54) 9(-1.27,-5.08) 10(1.27,-5.08)
C0201_NO_SS
  rect 0.254x0.305 smd: 1(-0.318,0) 2(0.318,0)
C0402_NO_SS
  rect 0.406x0.508 smd: 1(-0.406,0) 2(0.406,0)
C0402_NO_SS#2
  rect 0.406x0.508 smd: 1(-0.508,0) 2(0.508,0)
DB714
  rect 0.762x1.651 smd: 1(-1.27,1.587) 2(0,1.587) 3(1.27,1.587) 4(1.27,-1.587) 5(0,-1.587) 6(-1.27,-1.587)
FBUS_RS_96_ECL
  round 1.524 hole 1.524 unplated: (4,-1) (4,-9) (4,-13) (4,-21) (4,-25) (4,-33) (4,-37) (4,-45)
  round 2.108 hole 2.108 unplated: (4,-5) (4,-17) (4,-29) (4,-41)
  rect 1.016x1.016 hole 0.701: A1(0,0) B1(-2,0) C1(-4,0) D1(-6,0)
  round 1.016 hole 0.701: A2(0,-2) A3(0,-4) A4(0,-6) A5(0,-8) A6(0,-10) A7(0,-12) A8(0,-14) A9(0,-16) A10(0,-18) A11(0,-20) A12(0,-22) A13(0,-24) A14(0,-26) A15(0,-28) A16(0,-30) A17(0,-32) A18(0,-34) A19(0,-36) A20(0,-38) A21(0,-40) A22(0,-42) A23(0,-44) A24(0,-46) B2(-2,-2) B3(-2,-4) B4(-2,-6) B5(-2,-8) B6(-2,-10) B7(-2,-12) B8(-2,-14) B9(-2,-16) B10(-2,-18) B11(-2,-20) B12(-2,-22) B13(-2,-24) B14(-2,-26) B15(-2,-28) B16(-2,-30) B17(-2,-32) B18(-2,-34) B19(-2,-36) B20(-2,-38) B21(-2,-40) B22(-2,-42) B23(-2,-44) B24(-2,-46) C2(-4,-2) C3(-4,-4) C4(-4,-6) C5(-4,-8) C6(-4,-10) C7(-4,-12) C8(-4,-14) C9(-4,-16) C10(-4,-18) C11(-4,-20) C12(-4,-22) C13(-4,-24) C14(-4,-26) C15(-4,-28) C16(-4,-30) C17(-4,-32) C18(-4,-34) C19(-4,-36) C20(-4,-38) C21(-4,-40) C22(-4,-42) C23(-4,-44) C24(-4,-46) D2(-6,-2) D3(-6,-4) D4(-6,-6) D5(-6,-8) D6(-6,-10) D7(-6,-12) D8(-6,-14) D9(-6,-16) D10(-6,-18) D11(-6,-20) D12(-6,-22) D13(-6,-24) D14(-6,-26) D15(-6,-28) D16(-6,-30) D17(-6,-32) D18(-6,-34) D19(-6,-36) D20(-6,-38) D21(-6,-40) D22(-6,-42) D23(-6,-44) D24(-6,-46)
L4532
  rect 1.219x2.794 smd: 1(-2.108,0) 2(2.108,0)
LLP6_65M_WG2P5_L2P2_EP
  rect 0.61x0.254 smd: 1(-1.25,0.65) 2(-1.25,0) 3(-1.25,-0.65) 4(1.25,-0.65) 5(1.25,0) 6(1.25,0.65)
  rect 0.762x1.219 smd: 7(0,0)
LLP48_P5M_7X7_EP
  rect 0.61x0.254 smd: 1(-3.404,2.751) 2(-3.404,2.251) 3(-3.404,1.751) 4(-3.404,1.25) 5(-3.404,0.75) 6(-3.404,0.25) 7(-3.404,-0.25) 8(-3.404,-0.75) 9(-3.404,-1.25) 10(-3.404,-1.75) 11(-3.404,-2.25) 12(-3.404,-2.751) 25(3.404,-2.751) 26(3.404,-2.251) 27(3.404,-1.751) 28(3.404,-1.25) 29(3.404,-0.75) 30(3.404,-0.25) 31(3.404,0.25) 32(3.404,0.75) 33(3.404,1.25) 34(3.404,1.75) 35(3.404,2.25) 36(3.404,2.751)
  rect 0.254x0.61 smd: 13(-2.751,-3.404) 14(-2.251,-3.404) 15(-1.751,-3.404) 16(-1.25,-3.404) 17(-0.75,-3.404) 18(-0.25,-3.404) 19(0.25,-3.404) 20(0.75,-3.404) 21(1.25,-3.404) 22(1.75,-3.404) 23(2.25,-3.404) 24(2.751,-3.404) 37(2.751,3.404) 38(2.251,3.404) 39(1.751,3.404) 40(1.25,3.404) 41(0.75,3.404) 42(0.25,3.404) 43(-0.25,3.404) 44(-0.75,3.404) 45(-1.25,3.404) 46(-1.75,3.404) 47(-2.25,3.404) 48(-2.751,3.404)
  rect 5.08x5.08 smd: 49(0,0)
LPS3008_472ML
  custom 0.286x0.286 smd: 1(-1.067,1.651) 2(1.067,1.651)
MELF-MLL41
  custom 0.445x0.445 smd: 1(-2.667,0) 2(2.667,0)
MOUNTING_HOLE
  round 4.826 hole 2.489: 1(0,0)
MSTBA_RA_200_2
  round 1.981 hole 1.422: 1(0,2.54) 2(0,-2.54)
NC7WV125_8P
  rect 0.711x0.305 smd: 1(0,0) 2(0,-0.508) 3(0,-0.991) 4(0,-1.499) 5(2.692,-1.499) 6(2.692,-0.991) 7(2.692,-0.508) 8(2.692,0)
NFM41P
  rect 1.27x1.6 smd: 1(-2.413,0) 3(2.413,0)
  rect 1.778x2.54 smd: 2(0,0)
RF_SMA_END_LAUNCH
  rect 5.08x0.343 smd: 1(0,0)
  rect 5.08x2.413 smd: 2(0,4.318) 3(0,-4.318) 4(0,4.318) 5(0,-4.318)
SC70_3
  rect 0.762x0.406 smd: 1(-1.081,0.65) 2(-1.081,-0.65) 3(1.081,0)
SC-MKT-LQA68A
  rect 0.6x0.23 smd: 1(-4.7,4) 2(-4.7,3.5) 3(-4.7,3) 4(-4.7,2.5) 5(-4.7,2) 6(-4.7,1.5) 7(-4.7,1) 8(-4.7,0.5) 9(-4.7,0) 10(-4.7,-0.5) 11(-4.7,-1) 12(-4.7,-1.5) 13(-4.7,-2) 14(-4.7,-2.5) 15(-4.7,-3) 16(-4.7,-3.5) 17(-4.7,-4) 35(4.7,-4) 36(4.7,-3.5) 37(4.7,-3) 38(4.7,-2.5) 39(4.7,-2) 40(4.7,-1.5) 41(4.7,-1) 42(4.7,-0.5) 43(4.7,0) 44(4.7,0.5) 45(4.7,1) 46(4.7,1.5) 47(4.7,2) 48(4.7,2.5) 49(4.7,3) 50(4.7,3.5) 51(4.7,4)
  rect 0.23x0.6 smd: 18(-4,-4.7) 19(-3.5,-4.7) 20(-3,-4.7) 21(-2.5,-4.7) 22(-2,-4.7) 23(-1.5,-4.7) 24(-1,-4.7) 25(-0.5,-4.7) 26(0,-4.7) 27(0.5,-4.7) 28(1,-4.7) 29(1.5,-4.7) 30(2,-4.7) 31(2.5,-4.7) 32(3,-4.7) 33(3.5,-4.7) 34(4,-4.7) 52(4,4.7) 53(3.5,4.7) 54(3,4.7) 55(2.5,4.7) 56(2,4.7) 57(1.5,4.7) 58(1,4.7) 59(0.5,4.7) 60(0,4.7) 61(-0.5,4.7) 62(-1,4.7) 63(-1.5,4.7) 64(-2,4.7) 65(-2.5,4.7) 66(-3,4.7) 67(-3.5,4.7) 68(-4,4.7)
  rect 7.7x7.7 smd: GND(0,0)
SC-MKT-SDC08A_LLP
  rect 0.599x0.3 smd: 1(-1.9,1.199) 2(-1.9,0.399) 3(-1.9,-0.399) 4(-1.9,-1.199) 5(1.9,-1.199) 6(1.9,-0.399) 7(1.9,0.399) 8(1.9,1.199)
  rect 2.591x2.997 smd: DAP(0,0)
SM_SOT23_5_WGP150
  rect 1.397x0.762 smd: 1(1.714,1.27) 2(1.714,0) 3(1.714,-1.27) 4(-1.714,-1.27) 5(-1.714,1.27)
SMA_V_CLR
  round 2.032 hole 1.676: 1(0,0) 2(2.54,2.54) 3(-2.54,2.54) 4(-2.54,-2.54) 5(2.54,-2.54)
SMD_SIZE0402
  rect 0.635x0.508 smd: 1(-0.635,0) 2(0.635,0)
SMD_SIZE0603
  rect 0.762x0.965 smd: 1(-0.813,0) 2(0.813,0)
SMD_SIZE0805
  rect 1.27x1.778 smd: 1(-1.27,0) 2(1.27,0)
SMD_SIZE1206
  rect 1.27x1.778 smd: 1(-0.381,0) 2(2.413,0)
SMD_SIZE1812R
  rect 1.651x2.54 smd: 1(-2.223,0) 2(2.223,0)
SMD_SIZE3216
  rect 1.524x1.27 smd: 1(-1.27,0) 2(1.27,0)
SOD323
  rect 0.61x0.61 smd: 1(-1.105,0) 2(1.105,0)
SOD_123
  rect 0.914x1.219 smd: 1(-1.638,0) 2(1.638,0)
SOIC6_100_WG272_L560
  rect 4.699x1.397 smd: 1(-3.454,2.54) 2(-3.454,0) 3(-3.454,-2.54) 4(3.454,-2.54) 5(3.454,0) 6(3.454,2.54)
SOIC8_050_WG244_L200
  rect 2.388x0.635 smd: 1(-2.489,1.905)
  oval 2.388x0.635 smd: 2(-2.489,0.635) 3(-2.489,-0.635) 4(-2.489,-1.905) 5(2.489,-1.905) 6(2.489,-0.635) 7(2.489,0.635) 8(2.489,1.905)
TFS123A
  rect 0.8x1.5 smd: 1(-2.54,-2.15) 2(0,-2.15) 3(2.54,-2.15) 6(2.54,2.15) 7(0,2.15) 8(-2.54,2.15)
  rect 1.5x0.8 smd: 4(4.3,-1.27) 5(4.3,1.27) 9(-4.3,1.27) 10(-4.3,-1.27)
TFS153F
  rect 0.6x1 smd: 1(-1.27,-2.3) 2(0,-2.3) 3(1.27,-2.3) 7(1.27,2.3) 8(0,2.3) 9(-1.27,2.3)
  rect 1x0.6 smd: 4(3.3,-1.27) 5(3.3,0) 6(3.3,1.27) 10(-3.3,1.27) 11(-3.3,0) 12(-3.3,-1.27)
TP_500X_50
  round 1.778 hole 1.27: 1(0,0)
TSOT-6
  rect 0.991x0.686 smd: 1(-1.001,0.95) 2(-1.001,0) 3(-1.001,-0.95) 4(1.001,-0.95) 5(1.001,0) 6(1.001,0.95)
VXB1_1127_12M288
  rect 3.81x1.499 smd: 1(-4.502,0) 2(4.502,0)

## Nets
+3.3V: H4.A23 H4.A24 H4.B23 H4.B24
+5V: H4.A1 H4.A2 H4.B1 H4.B2
GND: C4.2 C5.2 C6.2 C7.2 C8.2 C9.2 C14.2 C15.2 C16.2 C17.2 C18.2 C19.2 C21.2 C22.2 C23.2 C24.2 C25.1 C26.1 C27.1 C28.1 C29.2 C30.2 C31.2 C32.2 C33.2 C34.2 C35.2 C36.2 C39.2 C41.1 C42.1 C43.2 C44.1 C45.1 C46.2 C61.2 C62.2 C63.2 C64.2 C74.2 C75.1 C76.2 C77.2 C84.2 C85.1 C86.2 C87.2 C101.1 C102.1 C103.1 C104.1 C105.1 C106.1 C107.1 C111.1 C112.1 C113.1 C114.1 C115.1 C116.1 C117.1 C121.1 C122.1 C123.1 C124.1 C125.1 C126.1 C127.1 C128.1 C129.1 C130.1 C131.2 C132.1 C133.1 C141.1 C142.1 C143.1 C144.1 C145.1 C146.1 C147.1 C149.1 C151.1 C154.1 C155.1 C156.1 C159.1 C161.1 C165.1 C171.1 C175.2 C177.2 C201.2 C202.2 C203.2 C204.2 C205.2 C206.2 C211.2 C212.2 C213.2 C215.2 C216.2 C217.2 C218.2 C219.2 C221.2 C222.2 C223.2 C224.2 C225.2 C226.2 C231.2 C232.2 C233.2 C234.2 C235.2 C236.2 C237.2 C238.2 C241.1 C243.1 C244.1 C245.2 C246.2 C247.2 C249.2 C250.2 C251.2 C252.2 C261.1 C263.1 C264.1 C265.2 C266.2 C267.2 C269.2 C270.2 C271.2 D1.2(C) D3.2 D5.2 H3.9(I) H4.A3 H4.A22 H4.B22 H4.C1 H4.C2 H4.C4 H4.C5 H4.C6 H4.C7 H4.C8 H4.C9 H4.C10 H4.C11 H4.C12 H4.C13 H4.C14 H4.C15 H4.C16 H4.C17 H4.C18 H4.C19 H4.C20 H4.C21 H4.C22 H4.C23 H4.C24 H4.D1 H4.D4 H4.D5 H4.D6 H4.D7 H4.D8 H4.D9 H4.D10 H4.D11 H4.D14 H4.D15 H4.D16 JP10.1 JP10.2 JP11.1 JP11.2 MH1.1 MH2.1 MH3.1 MH4.1 MH5.1 POWER.2(GND) R21.2 R22.2 R23.2 R24.2 R25.2 R26.2 R32.2 R33.2 R35.2 R36.2 R71.2 R72.2 R73.2 R74.2 R75.2 R76.2 R77.2 R78.2 R91.2 R92.2 R93.2 R94.2 R95.2 R96.2 R97.2 R98.2 R101.2 R103.2 R105.2 R115.1 R122.1 R124.2 R126.1 R129.1 R134.2 R135.1 R139.1 R140.2 R149.1 R157.2 R158.1 R161.1 R164.1 R173.2 R203.2 R214.1 R216.2 R217.1 R219.2 R221.1 R234.1 R236.2 R237.1 R239.2 SAM_AMP_Q.2(SHIELD2) SAM_AMP_Q.3(SHIELD3) SAM_AMP_Q.4(SHIELD4) SAM_AMP_Q.5(SHIELD5) SMA_AMP_I.2(SHIELD2) SMA_AMP_I.3(SHIELD3) SMA_AMP_I.4(SHIELD4) SMA_AMP_I.5(SHIELD5) SMA_CLK.2(SHIELD2) SMA_CLK.3(SHIELD3) SMA_CLK.4(SHIELD4) SMA_CLK.5(SHIELD5) SMA_REF.2(SHIELD2) SMA_REF.3(SHIELD3) SMA_REF.4(SHIELD4) SMA_REF.5(SHIELD5) SWGI.1 SWGI.3 SWGI.5(GND) SWGI.7 SWGI.9 SWGI.11 SWGI.13 SWGI.15 SWGQ.1 SWGQ.3 SWGQ.5(GND) SWGQ.7 SWGQ.9 SWGQ.11 SWGQ.13 SWGQ.15 TP1.1 TP2.1 TP3.1 TP4.1 U1.3(AGND_3) U1.15(AGND_15) U1.18(AGND_18) U1.21(AGND_21) U1.63(DRGND) U1.65(AGND_65) U1.68(AGND_68) U1.GND U2.4(GND) U2.7(WP) U3.13(GND_13) U3.15(GND_15) U3.26(GND_26) U3.28(GND_28) U3.DAP U4.1(GND_1) U4.17(GND_17) U4.49(DAP_PAD) U5.1(GND_1) U5.2(GND_2) U5.3(GND_3) U5.5(GND_5) U5.6(GND_RFOUT) U5.7(GND_7) U5.8(GND_8) U5.9(GND_9) U5.11(GND_11) U5.12(GND_RFIN) U6.1(OE1_N) U6.4(GND) U11.3(GND) U11.DAP U12.2(GND) U13.3(GND) U13.DAP U14.2(GND) U15.3(GND) U15.DAP U16.3(GND) U16.7(DAP) U17.3(GND) U17.7(DAP) U18.1(GND_1) U18.2(GND_2) U18.3(GND_3) U18.4(GND_4) U18.6(GND_6) U18.7(GND_7) U18.8(GND_8) U18.9(GND_9) Y2.3(GND) Y3.3(GND) Z1.2 Z2.2 Z3.2 Z4.2 Z5.2 Z6.2
ADC_CLK_N: C173.1 C174.2 C177.1 R162.1 U1.26(CLK+)
ADC_CLK_P: C172.1 C174.1 C176.1 R162.2 U1.25(CLK-)
ADC_VIN_IN: C73.2 C75.2 L3.1 L7.2 R44.2 U1.67(VIN-I)
ADC_VIN_IP: C73.1 C74.1 L3.2 L10.2 R43.1 U1.66(VIN+I)
ADC_VIN_QN: C83.2 C85.2 L6.1 L8.2 R49.2 U1.19(VIN-Q)
ADC_VIN_QP: C83.1 C84.1 L6.2 L9.2 R48.1 U1.20(VIN+Q)
ADC_VRM_I: C41.2 C42.2 C43.1 R45.2 U1.2(VRMI)
ADC_VRM_Q: C44.2 C45.2 C46.1 R50.2 U1.16(VRMQ)
D0/1+I: H4.B5 U1.60(D0/1+I)
D0/1+Q: H4.B21 U1.28(D0/1+Q)
D0/1-I: H4.A5 U1.61(D0/1-I)
D0/1-Q: H4.A21 U1.29(D0/1-Q)
D2/3+I: H4.B6 U1.58(D2/3+I)
D2/3+Q: H4.B20 U1.30(D2/3+Q)
D2/3-I: H4.A6 U1.59(D2/3-I)
D2/3-Q: H4.A20 U1.31(D2/3-Q)
D4/5+I: H4.B7 U1.56(D4/5+I)
D4/5+Q: H4.B19 U1.32(D4/5+Q)
D4/5-I: H4.A7 U1.57(D4/5-I)
D4/5-Q: H4.A19 U1.33(D4/5-Q)
D6/7+I: H4.B8 U1.54(D6/7+I)
D6/7+Q: H4.B18 U1.34(D6/7+Q)
D6/7-I: H4.A8 U1.55(D6/7-I)
D6/7-Q: H4.A18 U1.35(D6/7-Q)
D8/9+I: H4.B9 U1.52(D8/9+I)
D8/9+Q: H4.B17 U1.36(D8/9+Q)
D8/9-I: H4.A9 U1.53(D8/9-I)
D8/9-Q: H4.A17 U1.37(D8/9-Q)
D10/11+I: H4.B10 U1.50(D10/11+I)
D10/11+Q: H4.B16 U1.38(D10/11+Q)
D10/11-I: H4.A10 U1.51(D10/11-I)
D10/11-Q: H4.A16 U1.39(D10/11-Q)
D12/13+I: H4.B11 U1.48(D12/13+I)
D12/13+Q: H4.B15 U1.40(D12/13+Q)
D12/13-I: H4.A11 U1.49(D12/13-I)
D12/13-Q: H4.A15 U1.41(D12/13-Q)
D14/15+I: H4.B12 U1.46(D14/15+I)
D14/15+Q: H4.B14 U1.42(D14/15+Q)
D14/15-I: H4.A12 U1.47(D14/15-I)
D14/15-Q: H4.A14 U1.43(D14/15-Q)
DVGA_CLK: R4.1 R67.2 R77.1 SWGI.4 U3.2(A4/CLK/UPA)
DVGA_CSC: R7.1 R65.2 R75.1 SWGI.8 U3.32(A2/CS/S1A)
DVGA_SDI: R5.1 R66.2 R76.1 SWGI.6 U3.1(A3/SDI/DNA)
DVGA_SDO: R6.1 R64.2 R74.1 SWGI.10 U3.31(A1/SDO/S0A)
OUTCLK+: H4.A13 U1.45(OUTCLK-)
OUTCLK-: H4.B13 U1.44(OUTCLK+)
REGSEQ: C252.1 R202.1 R206.1 R208.1 R220.1 R221.2
SCB: H4.D21 R1.2
SCLK: H4.D24 R3.2 R4.2
SDI: H4.D22 R2.2 R5.2
SDO: H4.D23 R6.2
VA1P8: C23.1 C24.1 C27.2 C28.2 C270.1 C271.1 TP17.1 U1.1(VA1P8_1) U1.17(VA1P8_17) Z5.3
VA3P0: C21.1 C22.1 C25.2 C26.2 C33.1 C34.1 C35.1 C36.1 C250.1 C251.1 R220.2 TP15.1 U1.4(VA3P0_4) U1.14(VA3P0_14) U1.22(VA3P0_22) U1.64(VA3P0_64) Z4.3
VAMP: C61.1 C62.1 C63.1 C64.1 C203.1 C204.1 C205.1 C206.1 R31.2 R34.2 R61.1 R62.1 R63.1 R64.1 R65.1 R66.1 R67.1 R68.1 R81.1 R82.1 R83.1 R84.1 R85.1 R86.1 R87.1 R88.1 TP11.1 U3.14(+5V_14) U3.27(+5V_27) Z1.3
VIO1P8: C31.1 C32.1 C225.1 C226.1 TP18.1 U1.62(VDR) Z6.3
VPLL: C101.2 C102.2 C103.2 C104.2 C105.2 C106.2 C107.2 C111.2 C112.2 C113.2 C114.2 C115.2 C116.2 C117.2 C134.2 C216.1 C217.1 JP1.1 R113.2 R114.2 R116.1 TP12.1 U4.3(VCC1) U4.8(VCC2) U4.18(VCC4) U4.19(VCC5) U4.22(VCC6) U4.24(VCC7) U4.30(VCC8) U4.31(VCC9) U4.33(VCC10) Z2.3
VPLLIO: C121.2 C122.2 C123.2 C124.2 C125.2 C126.2 C127.2 C128.2 C129.2 C130.2 C175.1 C218.1 C219.1 R172.1 TP13.1 U4.13(VCC3) U4.37(VCC11) U4.40(VCC12) U4.43(VCC13) U4.46(VCC14) U6.5(A2) U6.7(OE2_N) U6.8(VCC) Z3.3
VREF: C29.1 C30.1 U1.9(VREF)
VREFOSC: C146.2 C235.1 C236.1 L12.2 R121.2 TP19.1 Y3.6(VS)
VRNI: C1.2 C2.2 C3.2 C5.1 C7.1 C9.1 U1.5(VRNI_5) U1.6(VRNI_6)
VRNQ: C11.2 C12.2 C13.2 C15.1 C17.1 C19.1 U1.12(VRNQ_12) U1.13(VRNQ_13)
VRPI: C1.1 C2.1 C3.1 C4.1 C6.1 C8.1 U1.7(VRPI_7) U1.8(VRPI_8)
VRPQ: C11.1 C12.1 C13.1 C14.1 C16.1 C18.1 U1.10(VRPQ_10) U1.11(VRPQ_11)
VVCXO: C155.2 C156.2 C237.1 C238.1 L13.2 TP20.1 Y2.6(VS)
N16787386: C39.1 H4.D3 U2.1(A0) U2.2(A1) U2.3(A2) U2.8(VCC)
N16788767: H4.B3 U2.5(SDA)
N16789698: H4.C3 U2.6(SCL)
N16910308: C214.1 C215.1 R204.2 U11.5(OUT) Z2.1 Z3.1
N16910312: R201.2 R202.2 U11.8(S\D\)
N16910365: C211.1 C212.1 C221.1 C222.1 C231.1 C232.1 L11.2 R201.1 R205.1 R207.1 R211.1 R212.1 R231.1 R232.1 U11.4(IN) U16.6(IN) U17.6(IN) Z1.1
N16910417: C214.2 R203.1 R204.1 U11.6(ADJ)
N16910454: C213.1 U11.1(BYPASS)
N16910619: C201.1 C202.1 D1.1(A) L11.1 POWER.1(5V)
N16910872: C223.1 C224.1 U16.1(OUT) Z6.1
N16914166: C141.2 R101.1 R102.1 U4.4(CLKUWIRE)
N16914374: C142.2 R103.1 R104.1 U4.5(DATAUWIRE)
N16914480: C143.2 R105.1 R106.1 U4.6(LEUWIRE)
N16915833: C144.2 R111.1 R113.1 U4.27(SYNC*)
N16916282: C145.2 R112.1 R114.1 U4.11(GOE)
N16917059: C161.2 C162.2 C163.2 R148.2
N16917150: C162.1 C163.1 R149.2
N16918738: C151.2 C152.2 C153.2 R125.2 R127.1
N16918746: C152.1 C153.1 R126.2
N16919303: R148.1 U4.32(CPOUT2)
N16919573: R125.1 R128.1 U4.23(CPOUT1)
N16925537: C157.2 R132.1 R134.1 R136.2
N16925643: C158.2 R133.1 R135.2 R137.2
N16932838: R133.2 Y2.5(RF*)
N16933075: R131.1 R132.2 Y2.4(RF)
N16933884: C157.1 U4.29(OSCIN*)
N16934135: C158.1 U4.28(OSCIN)
N16936974: H3.1(A) R111.2
N16941769: H3.10(J) JP1.2
N16945927: C148.1 R123.2 R124.1 R163.2
N16961545: C147.2 R121.1 R122.2 Y3.1(VTUNE)
N16966744: C149.2 U4.21(CLKIN0*)
N16967372: C148.2 U4.20(CLKIN0)
N17069889: C172.2 R159.2 T4.1
N17069899: R151.1 R152.1 R154.1 R156.2 R157.1 R159.1 T4.5
N17069913: C173.2 R160.2 T4.3
N17069923: R153.1 R155.1 R158.2 R160.1 T4.4
N17069969: R153.2 U4.41(CLKOUT2)
N17078917: R152.2 R171.2 U4.42(CLKOUT2*)
N17080344: R154.2 U4.39(CLKOUT1*)
N17080704: R155.2 U4.38(CLKOUT1)
N17085389: C134.1 U4.36(BIAS)
N17126548: H3.2(E) R102.2
N17128064: H3.4(F) R104.2
N17128444: H3.6(G) R106.2
N17145640: R115.2 U4.25(CLKIN1)
N17146037: R116.2 U4.26(CLKIN1*)
N17171025: C133.2 U4.16(DLD_BYP)
N17184058: C131.1 U4.9(LDOBYP1)
N17184483: C132.2 U4.10(LDOBYP2)
N17196113: H3.3(B) R112.2
N17380188: C248.1 C249.1 R218.2 U13.5(OUT) Z4.1
N17380190: C244.2 C245.1 C246.1 L22.2 R211.2 R217.2 TP14.1 U13.4(IN) U13.8(S\D\)
N17380250: C248.2 R218.1 R219.1 U13.6(ADJ)
N17380270: C247.1 U13.1(BYPASS)
N17418092: C233.1 C234.1 L12.1 L13.1 U17.1(OUT)
N17540898: C171.2 R161.2 T4.2
N17556627: TP5.1 U4.12(LD)
N17951100: C72.1 C79.2 R42.2
N17951224: C72.2 L2.1
N17951350: C71.2 L1.1
N17951477: C71.1 C79.1 R41.2
N18225867: R131.2 R156.1
N19850383: C176.2 U6.6(Y1)
N19858006: R172.2 R173.1 U5.4(VO) U6.2(A1) U18.5(VO)
N19891198: C80.2 C82.1 R47.2
N19891210: C82.2 L5.1
N19891220: C81.2 L4.1
N19891226: C80.1 C81.1 R46.2
N19915962: R86.2 R96.1 SWGQ.6 U3.16(B0/GND)
N19915964: R83.2 R93.1 SWGQ.12 U3.8(B3/GND/DNB)
N19915966: R84.2 R94.1 SWGQ.10 U3.9(B2/GND/S1B)
N19916068: R85.2 R95.1 SWGQ.8 U3.10(B1/GND/S0B)
N19916070: R81.2 R91.1 SWGQ.16 U3.6(B5/GND)
N19916116: R82.2 R92.1 SWGQ.14 U3.7(B4/GND/UPB)
N19916160: R88.2 R98.1 SWGQ.2 U3.20(LATB/GND)
N19916168: R87.2 R97.1 SWGQ.4 U3.19(ENB)
N19927061: R42.1 U3.23(OPA-)
N19930621: R47.1 U3.18(OPB-)
N19931174: R41.1 U3.24(OPA+)
N19978393: R63.2 R73.1 SWGI.12 U3.25(A0/GND)
N19978493: R61.2 R71.1 SWGI.16 U3.21(LATA/GND)
N19978527: R62.2 R72.1 SWGI.14 U3.22(ENA)
N19978547: R68.2 R78.1 SWGI.2 U3.3(A5/GND)
N20035799: C268.1 C269.1 R238.2 U15.5(OUT) Z5.1
N20035801: C264.2 C265.1 C266.1 L24.2 R231.2 R237.2 TP16.1 U15.4(IN) U15.8(S\D\)
N20035851: C268.2 R238.1 R239.1 U15.6(ADJ)
N20035871: C267.1 U15.1(BYPASS)
N20095878: R1.1 U1.27(CSB)
N20110879: R2.1 U1.24(SDI)
N20111750: R3.1 U1.23(SCLK)
N20255780: C54.2 U3.30(IPA+)
N20256222: C53.2 U3.29(IPA-)
N20256983: C57.2 U3.11(IPB+)
N20256985: C58.2 U3.12(IPB-)
N20301482: R31.1 R32.1 U3.4(MOD0)
N20301496: R33.1 R34.1 U3.5(MOD1)
N20322732: C52.2 R23.1 T1.6
N20327745: C52.1 R22.1
N20329493: C51.1 R21.1 SMA_AMP_I.1(CENTER)
N20339212: C54.1 T1.3
N20339230: C53.1 T1.1
N20345473: C56.2 R26.1 T2.4
N20345514: C58.1 T2.3
N20345516: C57.1 T2.1
N20345544: C56.1 R25.1
N20345548: C55.1 R24.1 SAM_AMP_Q.1(CENTER)
N20345595: C55.2 T2.6
N20471540: H4.D20 R7.2
N20575382: C76.1 C77.1 R43.2 R44.1 R45.1
N20577573: C86.1 C87.1 R48.2 R49.1 R50.1
N20588383: C241.2 D2.2 R212.2 R213.1 U12.5(VIN)
N20593441: C242.2 D3.1 L21.1 U12.6(SW)
N20594215: C243.2 L21.2 L22.1 R215.1
N20600657: C242.1 D2.1 U12.1(BOOST)
N20605120: R213.2 R214.2 U12.4(EN)
N20610525: R215.2 R216.1 U12.3(FB)
N20652482: C263.2 L23.2 L24.1 R235.1
N20652502: C262.1 D4.1 U14.1(BOOST)
N20652526: C262.2 D5.1 L23.1 U14.6(SW)
N20652532: R235.2 R236.1 U14.3(FB)
N20652558: C261.2 D4.2 R232.2 R233.1 U14.5(VIN)
N20652626: R233.2 R234.2 U14.4(EN)
N20699758: R205.2 R206.2 U16.4(EN)
N20706015: R207.2 R208.2 U17.4(EN)
N20974895: R123.1 Y3.4(RF)
N21782541: R171.1 U5.10(VIN) U18.10(VIN)
N21835550: R151.2 SMA_CLK.1(CENTER)
N21864410: C154.2 R127.2 Y2.1(VTUNE)
N22064666: R46.1 U3.17(OPB+)
N22090895: R163.1 R164.2 SMA_REF.1(CENTER)
N22120084: C159.2 C160.2 C164.2 R128.2 R130.1
N22120092: C160.1 C164.1 R129.2
N22142576: C165.2 R130.2 R138.2
N22153853: C150.1 D6.1 R140.1
N22154582: C166.1 D6.2 R139.2
N22165309: C166.2 R136.1 Y4.1
N22166052: C150.2 R137.1 Y4.2
N22186748: D6.3 R138.1
N22241799: C88.2 L5.2 L8.1
N22241801: C88.1 L4.2 L9.1
N22241811: C78.2 L2.2 L7.1
N22241813: C78.1 L1.2 L10.1
N22290747: C51.2 T1.4
N22296932: R35.1 T1.2
N22299452: R36.1 T2.2

Pads without a net: H3 5 7 8; H4 A4 B4 D2 D12 D13 D17 D18 D19; T1 5; T2 5; U4 2 7 14 15 34 35 44 45 47 48; U6 3; U11 2 7; U13 2 7; U15 2 7; U16 2 5; U17 2 5; Y2 2; Y3 2 5

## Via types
v1: diameter 0.508, hole 0.254, TOP to BOTTOM, 418 vias
v2: diameter 0.686, hole 0.33, TOP to BOTTOM, 193 vias
v3: diameter 0.635, hole 0.254, TOP to BOTTOM, 364 vias
v4: diameter 0.406, hole 0.305, TOP to BOTTOM, 3 vias

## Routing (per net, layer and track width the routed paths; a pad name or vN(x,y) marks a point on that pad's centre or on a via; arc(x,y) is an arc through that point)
+3.3V: length 8
  BOTTOM w0.508: H4.A24 H4.B24 H4.B23 H4.A23 H4.A24
+5V: length 8
  BOTTOM w0.508: H4.B2 H4.B1 H4.A1 H4.A2 H4.B2
GND: length 2345.1
  TOP w0.203: U1.65 93.08,117.31 v1(93.79,116.6) ; v1(73.89,112.93) 74.14,112.95 U3.13 ; v1(94.98,116.6) 94.08,117.5 U1.63 ; 90.88,109.19 91.41,109.19 91.58,109.36 U1.18 91.58,110.12 92.33,110.87 92.33,111.12 ; v1(75.08,115.32) 75.14,115.58 U3.26 ; 92.33,111.12 U1.15 ; 92.33,111.12 v1(92.6,111.39) ; U4.17 91.45,68.54 v1(92.2,69.29) ; 90.88,119.05 91.41,119.05 91.58,118.88 U1.68 91.58,118.27 92.63,117.22 92.63,116.64 v1(92.6,116.6) 92.07,117.12 U1.3 ; U3.28 74.14,115.59 v1(73.89,115.32) ; U4.1 89.45,73.31 v1(90.93,71.83) ; U3.15 75.14,112.95 v1(75.08,112.93) ; 100.25,17.63 100.77,17.63 U17.3 v2(100.77,18.64) ; v1(93.79,111.14) 93.08,110.43 U1.21 ; v2(84.71,67.34) 85.67,68.3 C132.1
  TOP w0.254: U6.1 v1(92.05,91.77) ; U6.4 v1(92.05,90.27)
  TOP w0.305: U11.3 v1(77.69,15.47)
  TOP w0.343: v3(120.95,78.38) 120.96,78.39 U16.3
  TOP w0.381: 89.23,110.67 C15.2 C17.2 C19.2 v1(86.97,110.67) ; 87.68,113.49 C18.2 C14.2 88.93,113.49 89.2,113.77 ; 87.68,113.49 v1(87.68,113.89) 87.68,114.27 ; 87.68,113.49 C16.2 86.79,113.49 ; 96.88,65.43 C115.1 v1(97.61,65.43) ; 96.88,65.43 96.88,65.18 v1(97.16,64.9) ; 96.88,65.43 96.88,66.24 v1(97.64,66.24) ; v1(88.14,118.77) C42.1 ; v1(100.89,59.39) C154.1 100.89,58.7 v3(101.52,58.7) ; 86.79,113.49 v1(86.16,113.49) ; 86.79,113.49 v1(86.79,113.89) 86.79,114.27 ; U15.3 61.99,63 v1(61.59,63.4) ; 87.68,114.27 C8.2 86.79,114.27 ; 87.68,114.27 C6.2 C4.2 89.31,114.27 ; v1(88.14,109.83) C44.1 C45.1 v1(88.14,108.94) ; 86.79,114.27 v1(86.11,114.27) ; U13.3 47.77,64.42 v1(47.37,64.82) ; v1(88.14,117.93) C41.1 ; 103.63,139.01 C39.2
  TOP w0.406: 96.32,141.88 SWGI.7 ; SWGI.7 97.41,142.98 ; SWGI.7 98.5,141.88 ; SWGI.7 97.41,140.79 ; 109.42,50.6 R164.1 109.42,51.71 ; SMA_REF.2 110.67,49.17 ; SMA_REF.2 111.99,47.85 ; SMA_REF.2 109.35,47.85 ; SMA_REF.2 110.67,46.53 ; 103.2,84.35 JP11.1 ; JP11.1 105.33,84.35 ; JP11.1 104.27,85.42 ; JP11.1 104.27,83.29 ; 47.35,11.81 POWER.2 ; POWER.2 48.64,13.11 ; POWER.2 46.05,13.11 ; POWER.2 47.35,14.4 ; 101.58,133.68 U2.4 100.08,133.06 ; 80.34,152.76 R92.2 81.46,152.76 ; C237.2 110.95,23.52 ; C237.2 110.01,24.59 ; C237.2 109.07,23.52 ; TP4.1 106.81,37.52 ; TP4.1 105.61,38.71 ; TP4.1 105.61,36.32 ; TP4.1 104.42,37.52 ; MH3.1 13.59,11.63 ; MH3.1 13.59,6.2 ; MH3.1 16.31,8.92 ; MH3.1 10.87,8.92 ; H4.C24 118.96,91.97 ; H4.C24 117.34,91.97 ; H4.C24 118.15,91.16 ; H4.C24 118.15,92.79 ; 74.73,141.88 SWGQ.9 ; SWGQ.9 75.82,142.98 ; SWGQ.9 76.91,141.88 ; SWGQ.9 75.82,140.79 ; 117.3,76.71 C225.2 116.23,77.65 ; 97.23,63.98 C105.1 97.85,64.54 ; 98.3,75.87 R149.1 99.42,75.87 ; 86.26,94.84 R173.2 86.26,95.96 ; MH5.1 16.31,81.31 ; MH5.1 10.87,81.31 ; MH5.1 13.59,84.02 ; MH5.1 13.59,78.59 ; 118.96,131.97 H4.C4 117.34,131.97 ; 66.42,17.83 JP10.2 ; JP10.2 67.49,18.9 ; JP10.2 65.35,18.9 ; JP10.2 66.42,19.96 ; 88.75,81.23 R157.2 88.75,82.35 ; 107.85,15.11 C231.2 106.91,16.18 ; MH2.1 125.53,148.62 ; MH2.1 122.81,151.33 ; MH2.1 120.09,148.62 ; MH2.1 122.81,145.9 ; v3(51.21,71.27) 51.21,72.47 ; v3(51.21,71.27) 51.21,70.08 ; v3(51.21,71.27) 52.78,71.27 ; 73.28,142.98 SWGQ.7 74.37,141.88 ; 89.79,140.79 SWGI.1 ; SWGI.1 88.7,141.88 ; SWGI.1 89.79,142.98 ; SWGI.1 90.88,141.88 ; 87.75,88.6 U5.1 ; U5.1 88.56,87.99 ; U5.1 88.56,89.2 ; 99.42,67.79 R135.1 99.97,67.17 ; TP1.1 121.62,57.58 ; TP1.1 121.62,55.19 ; TP1.1 120.42,56.39 ; TP1.1 122.81,56.39 ; 99.39,152.76 R74.2 100.51,152.76 ; TP2.1 58.24,114.15 ; TP2.1 57.05,115.34 ; TP2.1 55.85,114.15 ; TP2.1 57.05,112.95 ; 84.43,45.92 C146.1 84.43,47.04 ; 64.01,54.64 R237.1 64.01,53.52 ; 92.33,140.79 SWGI.3 ; SWGI.3 91.24,141.88 ; SWGI.3 93.42,141.88 ; SWGI.3 92.33,142.98 ; 92.89,152.76 R77.2 91.77,152.76 ; 90.21,62.41 R124.2 90.83,61.85 ; 119.34,95.97 H4.B22 ; H4.B22 120.96,95.97 ; H4.B22 120.15,95.16 ; H4.B22 120.15,96.79 ; 97.97,152.76 R75.2 96.85,152.76 ; 101.78,24.82 C233.2 ; C233.2 102.72,25.88 ; C233.2 102.72,23.75 ; H4.C23 118.15,94.79 ; H4.C23 118.96,93.97 ; H4.C23 117.34,93.97 ; H4.C23 118.15,93.16 ; SMA_REF.5 110.67,44.09 ; SMA_REF.5 111.99,42.77 ; SMA_REF.5 110.67,41.45 ; SMA_REF.5 109.35,42.77 ; SWGQ.11 79.45,141.88 ; SWGQ.11 78.36,140.79 ; SWGQ.11 77.27,141.88 ; SWGQ.11 78.36,142.98 ; 47.52,58.22 C244.1 46.74,58.9 ; 83.36,75.26 SMA_CLK.5 ; SMA_CLK.5 83.36,77.9 ; SMA_CLK.5 84.68,76.58 ; SMA_CLK.5 82.04,76.58 ; C271.2 62.48,71.73 ; C271.2 62.48,70.36 ; C271.2 63.27,71.04 ; v3(78.31,27.28) 78.31,28.47 ; v3(78.31,27.28) 78.31,26.09 ; v3(78.31,27.28) 76.73,27.28 ; v3(78.31,27.28) 79.88,27.28 ; 117.34,137.97 H4.C1 ; H4.C1 118.15,138.79 ; H4.C1 118.15,137.16 ; H4.C1 118.96,137.97 ; 82.35,141.88 SWGQ.15 ; SWGQ.15 83.44,140.79 ; SWGQ.15 83.44,142.98 ; SWGQ.15 84.53,141.88 ; 120.09,8.92 MH4.1 ; MH4.1 125.53,8.92 ; MH4.1 122.81,6.2 ; MH4.1 122.81,11.63 ; 50.09,57.15 C245.2 ; C245.2 v1(51.16,56.21) ; C245.2 51.16,58.09 ; C245.2 v1(52.22,57.15) ; 66.42,20.37 JP10.1 ; JP10.1 67.49,21.44 ; JP10.1 66.42,22.5 ; JP10.1 65.35,21.44 ; SMA_REF.3 105.59,49.17 ; SMA_REF.3 106.91,47.85 ; SMA_REF.3 104.27,47.85 ; SMA_REF.3 105.59,46.53 ; 72.72,152.76 R95.2 73.84,152.76 ; SMA_REF.4 106.91,42.77 ; SMA_REF.4 105.59,41.45 ; SMA_REF.4 104.27,42.77 ; SMA_REF.4 105.59,44.09 ; 86.26,92.36 U5.5 ; U5.5 86.86,93.17 ; U5.5 85.65,93.17 ; 60.78,34.16 C205.2 59.71,35.1 ; U5.9 84.76,88.6 ; U5.9 83.96,89.2 ; U5.9 83.96,87.99 ; 65.81,69.06 Z5.2 ; Z5.2 64.24,70.26 ; Z5.2 67.39,70.26 ; Z5.2 65.81,71.45 ; H3.9 62.15,49.96 ; H3.9 63.2,48.92 ; H3.9 61.11,48.92 ; 94.87,140.79 SWGI.5 ; SWGI.5 95.96,141.88 ; SWGI.5 93.78,141.88 ; SWGI.5 94.87,142.98 ; C267.2 v1(59.11,60.32) ; C267.2 59.11,59.21 ; C267.2 58.48,59.77 ; 94.31,152.76 R76.2 95.43,152.76 ; 76.38,152.76 R94.2 75.26,152.76 ; U5.7 84.76,91.14 ; U5.7 83.96,90.53 ; U5.7 83.96,91.74 ; v1(49.17,64.82) v1(47.37,64.82) v1(45.57,64.82) ; 104.47,152.76 R72.2 105.59,152.76 ; 116.15,137.16 H4.D1 ; H4.D1 115.34,137.97 ; H4.D1 116.96,137.97 ; H4.D1 116.15,138.79 ; U5.3 88.56,91.74 ; U5.3 87.75,91.14 ; U5.3 88.56,90.53 ; 64.57,141.88 SWGQ.1 ; SWGQ.1 65.66,140.79 ; SWGQ.1 65.66,142.98 ; 76.96,76.58 SMA_CLK.4 ; SMA_CLK.4 78.28,75.26 ; SMA_CLK.4 78.28,77.9 ; SMA_CLK.4 79.6,76.58 ; SWGI.15 108.66,141.88 ; SWGI.15 107.57,140.79 ; SWGI.15 106.48,141.88 ; SWGI.15 107.57,142.98 ; 80.9,140.79 SWGQ.13 ; SWGQ.13 81.99,141.88 ; SWGQ.13 79.81,141.88 ; SWGQ.13 80.9,142.98 ; C202.2 43.87,21.34 ; C202.2 43.87,19.76 ; C202.2 43.18,20.55 ; 121.34,133.97 H4.A3 ; H4.A3 122.96,133.97 ; H4.A3 122.15,133.16 ; H4.A3 122.15,134.79 ; 116.96,131.97 H4.D4 115.34,131.97 ; 117.34,135.97 H4.C2 ; H4.C2 118.96,135.97 ; H4.C2 118.15,135.16 ; H4.C2 118.15,136.79 ; TP3.1 78.49,70.33 ; TP3.1 79.68,69.14 ; TP3.1 78.49,67.94 ; TP3.1 77.29,69.14 ; v1(56.46,71.37) C251.2 ; C251.2 v1(57.25,72.06) ; C251.2 55.68,72.06 ; C251.2 56.46,72.75 ; Z6.2 118.44,82.55 ; Z6.2 117.25,80.98 ; Z6.2 119.63,80.98 ; Z6.2 118.44,79.4 ; 123.16,82.45 C223.2 122.22,83.52 ; C249.2 v1(52.4,63.53) ; C249.2 v1(50.01,63.53) ; C249.2 v1(51.21,62.59) ; 86.92,86.57 U5.12 ; U5.12 88.13,86.57 ; U5.12 87.53,87.37 ; 73.38,96.39 R24.2 73.38,97.51 ; 104.27,80.75 JP11.2 ; JP11.2 104.27,82.88 ; JP11.2 103.2,81.81 ; JP11.2 105.33,81.81 ; 73.38,131.85 R21.2 73.38,130.73 ; v1(44.91,61.7) C247.2 v1(44.4,61.19) ; 71.3,152.76 R96.2 70.18,152.76 ; SWGI.13 106.12,141.88 ; SWGI.13 105.03,140.79 ; SWGI.13 103.94,141.88 ; SWGI.13 105.03,142.98 ; 71.7,71.73 C270.2 70.64,72.67 ; 84.89,26.09 v3(84.89,27.28) ; v3(84.89,27.28) 84.89,28.47 ; v3(84.89,27.28) 83.31,27.28 ; v3(84.89,27.28) 86.46,27.28 ; 85.05,68.76 C132.1 85.67,69.32 ; R219.2 v1(49.05,71.53) ; 61.7,56.79 C264.1 60.91,57.48 ; 64.21,55.73 C265.2 65.28,54.79 ; 82.04,81.66 SMA_CLK.2 ; SMA_CLK.2 83.36,82.98 ; SMA_CLK.2 83.36,80.34 ; v1(54.53,70.08) C250.2 ; C250.2 54.53,72.21 ; C250.2 v1(53.59,71.15) ; C250.2 55.47,71.15 ; SWGI.11 103.58,141.88 ; SWGI.11 101.4,141.88 ; SWGI.11 102.49,140.79 ; SWGI.11 102.49,142.98 ; 86.54,31.11 C217.2 85.85,31.9 ; 82.88,152.76 R91.2 84,152.76 ; H4.A22 122.96,95.97 ; H4.A22 121.34,95.97 ; H4.A22 122.15,95.16 ; H4.A22 122.15,96.79 ; 63.4,63.4 v1(61.59,63.4) 59.79,63.4 ; 103.84,139.57 C39.2 103.84,138.45 ; 68.76,152.76 R97.2 67.64,152.76 ; 84.38,93.17 U5.6 ; U5.6 85.59,93.17 ; U5.6 84.99,92.36 ; 118.15,95.16 H4.C22 ; H4.C22 117.34,95.97 ; H4.C22 118.96,95.97 ; H4.C22 118.15,96.79 ; 81.03,11.23 81.03,10.29 79.96,10.29 ; 59.94,145.9 MH1.1 ; MH1.1 57.23,148.62 ; MH1.1 62.66,148.62 ; MH1.1 59.94,151.33 ; 88.56,89.26 U5.2 ; U5.2 88.56,90.47 ; U5.2 87.75,89.87 ; U5.8 83.96,90.47 ; U5.8 84.76,89.87 ; U5.8 83.96,89.26 ; 49.86,56.06 R217.1 49.86,54.94 ; 119.23,71.98 C221.2 121.36,71.98 ; 85.65,86.57 U5.11 ; U5.11 86.86,86.57 ; U5.11 86.26,87.37 ; 76.96,81.66 SMA_CLK.3 ; SMA_CLK.3 78.28,80.34 ; SMA_CLK.3 78.28,82.98 ; SMA_CLK.3 79.6,81.66 ; 101.93,152.76 R73.2 103.05,152.76 ; 92.91,89.81 U6.4 93.57,90.27 ; 59.87,31.77 C206.2 59.18,32.56 ; 87.43,27.38 C216.2 88.37,28.45 ; C246.2 v1(52.35,59.84) ; C246.2 v1(51.41,58.65) ; C246.2 v1(51.41,61.04) ; 74.83,28.45 C218.2 75.77,27.38 ; 99.95,140.79 SWGI.9 ; SWGI.9 101.04,141.88 ; SWGI.9 98.86,141.88 ; SWGI.9 99.95,142.98 ; 76.68,31.11 C219.2 77.37,31.9 ; Z1.2 54.41,24.89 ; Z1.2 52.83,26.09 ; Z1.2 51.26,24.89 ; Z1.2 52.83,23.7 ; 44.78,19.13 C201.2 43.71,18.19 ; 108.03,27.48 C238.2 107.34,28.27 ; 96.57,60.96 R126.1 95.95,60.4 ; 78.92,152.76 R93.2 77.8,152.76 ; 97.85,75.77 C127.1 97.23,75.21 ; 65.1,152.76 R98.2 66.22,152.76
  TOP w0.508: R237.1 v3(64.57,54.08) 64.59,54.1 ; R173.2 v3(85.62,95.4) ; v3(60.91,55.96) C264.1 59.97,56.79 v3(59.94,56.82) ; v3(117.3,78.84) C225.2 v3(118.31,77.65) ; C105.1 97.23,64.82 v1(97.16,64.9) ; R126.1 v3(96.57,59.77) ; C122.1 96.57,74.83 96.29,74.55 v1(96.29,74.5) ; v2(106.58,136.22) U2.7 v2(103.61,136.22) ; v1(81.03,8.86) 81.03,10.29 82.27,10.29 v1(82.3,10.31) ; C126.1 v1(88.29,65.53) C121.1 ; R23.2 v1(76.58,129.77) ; v3(93.73,62.99) 93.75,62.97 93.75,62.41 ; U5.9 82.85,88.6 v3(82.83,88.62) ; v1(57.86,44.75) 57.84,44.73 C143.1 ; v1(100.94,73.58) C161.1 v1(100.36,74.17) ; v3(88.7,75.62) C130.1 v3(89.31,76.15) ; v3(121.11,77.14) U16.7 v3(122.99,77.14) ; v2(103.71,24.84) 103.68,24.82 C233.2 ; v3(66.47,58.42) C266.2 v3(65.58,59.64) ; R101.2 v3(54.36,36.98) ; v2(75.59,18.14) U11.DAP v2(79.12,18.14) ; C144.1 64.26,40.13 v1(64.29,40.16) ; 86.28,85.7 v3(86.26,85.72) U5.11 ; C101.1 v3(87.71,74.27) ; Y2.3 v2(113.94,72.34) ; Y2.3 v1(116.94,70.94) ; Y2.3 112.93,70.94 112.52,71.35 112.52,72.34 ; U2.4 v2(98.12,133.68) ; C204.2 v1(37.19,75.95) ; C204.2 v1(38.18,76.63) ; C204.2 v1(36.17,76.63) ; C235.2 95.86,23.72 v2(96.11,23.47) ; C235.2 v2(94.97,22.5) ; C235.2 94.08,23.72 v2(93.83,23.47) ; 89.26,117.09 C7.2 v1(88.04,117.09) C5.2 87.48,117.09 v1(87.12,117.45) ; R164.1 v3(110.01,51.16) ; C141.1 v3(54.36,37.87) ; U5.12 v3(87.53,85.62) ; v1(102.82,63.88) C155.1 C156.1 v1(103.71,63.86) ; U5.5 v3(86.26,93.98) ; v3(86.18,73.46) C111.1 v3(86.92,74.22) ; C226.2 v1(110.87,78.54) ; C226.2 v1(110.01,77.65) ; C226.2 v1(110.87,76.78) ; v2(88.19,25.93) 88.37,26.11 C216.2 89.54,27.38 v3(89.56,27.41) ; v1(107.85,17.32) C231.2 v1(109.12,16.18) ; C203.2 v1(41.48,75.72) ; C203.2 v1(39.12,75.72) ; C203.2 v3(40.23,74.63) ; v3(82.93,89.84) 82.96,89.87 U5.8 ; 89.56,89.84 v3(89.54,89.87) U5.2 ; R92.2 v1(80.9,153.39) ; v1(97.64,66.24) 98.17,66.78 R115.1 v1(98.63,67.11) ; v1(92.35,153.49) 92.33,153.47 R77.2 ; v1(104.78,17.42) 104.8,17.4 C232.2 v1(106.07,16.43) ; v3(71.7,74.19) C270.2 v3(73.05,72.67) 73.08,72.64 ; v1(89.23,152.76) R78.2 v1(89.79,153.54) ; C151.1 v3(98.17,61.29) ; v2(76.68,32.92) C219.2 v2(75.54,31.9) ; v3(96.67,82.4) R158.1 v3(97.31,81.79) ; v2(103.63,139.83) 103.63,139.01 v2(102.9,139.01) ; v2(106.96,19.56) 106.73,19.79 C234.2 105.51,18.82 v2(105.87,18.47) ; v3(116.59,84.84) 116.64,84.79 C224.2 v3(118.06,86.26) ; v1(108.28,152.76) R71.2 v1(107.57,153.54) ; v3(125.3,79.35) C222.2 v3(126.54,78.31) ; v3(66.5,55.7) 66.47,55.73 C265.2 65.28,56.9 v3(65.25,56.92) ; U5.3 v3(89.51,91.14) ; C125.1 v3(88.77,74.96) ; v3(120.32,70.54) 120.29,70.56 C221.2 v3(120.29,73.23) ; Y3.3 96.49,44.2 v1(96.44,44.25) ; C127.1 v1(97.23,76.86) ; R75.2 v1(97.41,153.38) ; R73.2 v1(102.49,153.38) ; R98.2 v1(65.66,153.39) ; C146.1 v1(83.81,46.48) ; R97.2 v1(68.2,153.39) ; R122.1 v1(83.81,43.28) ; v2(87.55,31.9) C217.2 v2(86.54,33.32) ; v3(93.62,63.7) 93.6,63.73 C149.1 ; C271.2 v3(61.67,71.04) ; C133.1 v3(90.96,63.78) ; R72.2 v1(105.03,153.38) ; R134.2 v1(100.48,71.37) ; R135.1 v1(100.53,67.79) ; v3(123.19,84.94) 123.16,84.91 C223.2 124.54,83.52 v3(124.56,83.54) ; v3(59.87,33.35) C206.2 v1(60.53,32.56) ; v3(65.41,61.47) 65.43,61.49 C269.2 v3(66.8,62.51) ; R157.2 v2(87.93,81.79) ; v2(109.98,22.5) 110.01,22.53 C237.2 ; v3(90.81,62.92) 90.83,62.89 R124.2 ; R26.2 v3(75.92,98.02) ; R74.2 v1(99.95,153.38) ; v3(46.74,57.48) C244.1 45.92,58.22 v3(45.9,58.19) ; R94.2 v1(75.82,153.39) ; v3(60.38,71.48) R221.1 v3(59.94,70.82) ; R25.2 v3(76.68,101.6) ; R217.1 v3(50.55,55.5) ; v3(61.95,35.1) C205.2 v1(60.78,36.17) ; R91.2 v1(83.44,153.39) ; C213.2 v1(74.6,18.01) ; R149.1 v1(98.86,76.66) ; R95.2 v1(73.28,153.39) ; C147.1 v1(83.92,42.39) ; v3(74.02,131.29) R21.2 ; R93.2 v1(78.36,153.39) ; R105.2 v3(57.96,45.62) ; R76.2 v1(94.87,153.38) ; U5.6 v3(84.99,94.03) ; R239.2 v3(63.37,70.08) ; C103.1 v3(91.97,63.73) ; v3(74.02,96.95) R24.2 ; v3(95.15,94.44) C175.2 v3(95.71,95) ; C252.2 v3(58.98,70.76) ; v1(58.17,42.19) C142.1 ; C145.1 v3(64.16,42.72) ; R22.2 v1(76.68,126.64) ; R96.2 v1(70.74,153.39) ; U5.1 v3(89.43,88.6) ; U5.7 v3(82.91,91.14)
  TOP w0.635: v1(99.8,16.38) U17.7 v1(102.69,16.38) ; 57.4,94.28 v3(57.4,93.55) SAM_AMP_Q.3 ; SAM_AMP_Q.2 v3(57.4,102.18) 57.4,102.92 ; SAM_AMP_Q.2 60.38,101.3 ; SAM_AMP_Q.2 v3(57.4,100.41) 57.4,99.67 ; 57.4,128.6 v3(57.4,127.86) SMA_AMP_I.3 ; 102.57,24.84 v2(101.42,24.84) ; 102.57,24.84 v2(102.57,25.81) ; 102.57,24.84 v2(103.71,24.84) ; v3(81.15,16.31) C215.2 v3(82.6,17.25) ; SMA_AMP_I.3 v3(57.4,126.09) 57.4,125.35 ; SMA_AMP_I.3 60.38,126.97 ; SAM_AMP_Q.3 v3(57.4,91.77) 57.4,91.03 ; SAM_AMP_Q.3 60.38,92.66 ; v2(108.84,23.47) 109.98,23.47 ; 109.98,23.47 v2(111.12,23.47) ; 109.98,23.47 v2(109.98,22.5) ; SMA_AMP_I.2 v3(57.4,134.72) 57.4,133.99 ; SMA_AMP_I.2 v3(57.4,136.5) 57.4,137.24 ; SMA_AMP_I.2 60.38,135.61 ; C212.2 v1(81.28,11.63) 81.28,10.54 81.03,10.29 ; C212.2 v1(81.28,14.22) ; C212.2 v1(82.37,12.98) ; v2(96.55,28.27) C236.2 97.28,28.27 v2(97.28,29.08) ; v2(73.25,27.38) C218.2 v1(74.83,26.04)
  TOP w0.762: D1.2 v1(34.19,21.21) ; D1.2 v1(34.19,25.17) ; D1.2 v1(32.56,23.22) ; v2(108.03,29.36) C238.2 v1(108.48,28.27) ; v1(96.42,38) 96.49,38.07 Y3.3 v1(98.4,41.43) ; C202.2 v1(44.81,20.55) 44.83,20.57 ; v1(44.78,16.76) C201.2 v1(45.85,18.19)
  GROUND_L2 w0.381: JP11.2 105.54,81.81 ; JP11.2 104.27,80.54 ; JP11.2 103,81.81 ; H4.C16 118.15,108.79 ; H4.C16 118.96,107.97 ; H4.C16 117.34,107.97 ; H4.C16 118.15,107.16 ; 91.24,141.88 SWGI.3 ; SWGI.3 93.42,141.88 ; SWGI.3 92.33,140.79 ; SWGI.3 92.33,142.98 ; JP10.2 67.69,18.9 ; JP10.2 65.15,18.9 ; JP10.2 66.42,17.63 ; 117.34,135.97 H4.C2 ; H4.C2 118.15,135.16 ; H4.C2 118.15,136.79 ; H4.C2 118.96,135.97 ; 116.15,107.16 H4.D16 ; H4.D16 116.96,107.97 ; H4.D16 115.34,107.97 ; H4.D16 116.15,108.79 ; H4.D9 116.96,121.97 ; H4.D9 116.15,122.79 ; H4.D9 115.34,121.97 ; H4.D9 116.15,121.16 ; H4.C1 118.15,138.79 ; H4.C1 118.15,137.16 ; H4.C1 118.96,137.97 ; H4.C1 117.34,137.97 ; SWGI.7 97.41,142.98 ; SWGI.7 98.5,141.88 ; SWGI.7 96.32,141.88 ; SWGI.7 97.41,140.79 ; H4.C7 118.96,125.97 ; H4.C7 118.15,126.79 ; H4.C7 117.34,125.97 ; H4.C7 118.15,125.16 ; SWGI.15 107.57,142.98 ; SWGI.15 106.48,141.88 ; SWGI.15 107.57,140.79 ; SWGI.15 108.66,141.88 ; H4.C19 118.15,102.79 ; H4.C19 118.96,101.97 ; H4.C19 118.15,101.16 ; H4.C19 117.34,101.97 ; 118.15,121.16 H4.C9 ; H4.C9 118.96,121.97 ; H4.C9 117.34,121.97 ; H4.C9 118.15,122.79 ; H4.D8 116.15,124.79 ; H4.D8 115.34,123.97 ; H4.D8 116.96,123.97 ; H4.D8 116.15,123.16 ; H4.C24 118.96,91.97 ; H4.C24 118.15,92.79 ; H4.C24 118.15,91.16 ; H4.C24 117.34,91.97 ; MH2.1 122.81,151.64 ; MH2.1 119.79,148.62 ; MH2.1 125.83,148.62 ; MH2.1 122.81,145.59 ; 78.49,67.69 TP3.1 ; TP3.1 78.49,70.59 ; TP3.1 79.93,69.14 ; TP3.1 77.04,69.14 ; MH5.1 13.59,84.33 ; MH5.1 13.59,78.28 ; MH5.1 10.57,81.31 ; MH5.1 16.61,81.31 ; 116.15,129.16 H4.D5 ; H4.D5 115.34,129.97 ; H4.D5 116.15,130.79 ; H4.D5 116.96,129.97 ; 78.36,140.79 SWGQ.11 ; SWGQ.11 79.45,141.88 ; SWGQ.11 77.27,141.88 ; SWGQ.11 78.36,142.98 ; H4.C13 118.15,114.79 ; H4.C13 117.34,113.97 ; H4.C13 118.15,113.16 ; H4.C13 118.96,113.97 ; 117.34,131.97 H4.C4 ; H4.C4 118.15,131.16 ; H4.C4 118.96,131.97 ; H4.C4 118.15,132.79 ; 98.86,141.88 SWGI.9 ; SWGI.9 99.95,142.98 ; SWGI.9 101.04,141.88 ; SWGI.9 99.95,140.79 ; MH3.1 16.61,8.92 ; MH3.1 13.59,5.89 ; MH3.1 10.57,8.92 ; MH3.1 13.59,11.94 ; H4.C10 118.15,120.79 ; H4.C10 117.34,119.97 ; H4.C10 118.15,119.16 ; H4.C10 118.96,119.97 ; 117.34,127.97 H4.C6 ; H4.C6 118.15,128.79 ; H4.C6 118.96,127.97 ; H4.C6 118.15,127.16 ; 105.59,41.63 SMA_REF.4 ; SMA_REF.4 104.44,42.77 ; SMA_REF.4 106.73,42.77 ; SMA_REF.4 105.59,43.92 ; 57.05,112.7 TP2.1 ; TP2.1 58.5,114.15 ; TP2.1 55.6,114.15 ; TP2.1 57.05,115.6 ; SMA_REF.2 110.67,49 ; SMA_REF.2 110.67,46.71 ; SMA_REF.2 109.52,47.85 ; SMA_REF.2 111.81,47.85 ; 120.17,56.39 TP1.1 ; TP1.1 121.62,54.94 ; TP1.1 123.06,56.39 ; TP1.1 121.62,57.84 ; POWER.2 47.35,14.61 ; POWER.2 45.85,13.11 ; POWER.2 48.84,13.11 ; POWER.2 47.35,11.61 ; 118.15,105.16 H4.C17 ; H4.C17 118.96,105.97 ; H4.C17 117.34,105.97 ; H4.C17 118.15,106.79 ; MH4.1 125.83,8.92 ; MH4.1 122.81,11.94 ; MH4.1 122.81,5.89 ; MH4.1 119.79,8.92 ; 83.36,80.52 SMA_CLK.2 ; SMA_CLK.2 83.36,82.8 ; SMA_CLK.2 82.22,81.66 ; SMA_CLK.2 84.51,81.66 ; H4.D15 116.96,109.97 ; H4.D15 115.34,109.97 ; H4.D15 116.15,109.16 ; H4.D15 116.15,110.79 ; SMA_REF.3 106.73,47.85 ; SMA_REF.3 104.44,47.85 ; SMA_REF.3 105.59,49 ; SMA_REF.3 105.59,46.71 ; 118.15,95.16 H4.C22 ; H4.C22 118.96,95.97 ; H4.C22 118.15,96.79 ; H4.C22 117.34,95.97 ; H4.D1 116.15,138.79 ; H4.D1 116.15,137.16 ; H4.D1 115.34,137.97 ; H4.D1 116.96,137.97 ; 116.15,119.16 H4.D10 ; H4.D10 116.96,119.97 ; H4.D10 116.15,120.79 ; H4.D10 115.34,119.97 ; 117.34,109.97 H4.C15 ; H4.C15 118.15,109.16 ; H4.C15 118.15,110.79 ; H4.C15 118.96,109.97 ; 115.34,111.97 H4.D14 ; H4.D14 116.15,111.16 ; H4.D14 116.15,112.79 ; H4.D14 116.96,111.97 ; H4.C5 118.96,129.97 ; H4.C5 118.15,129.16 ; H4.C5 117.34,129.97 ; H4.C5 118.15,130.79 ; TP4.1 105.61,38.96 ; TP4.1 104.16,37.52 ; TP4.1 105.61,36.07 ; TP4.1 107.06,37.52 ; 68.2,140.79 SWGQ.3 ; SWGQ.3 69.29,141.88 ; SWGQ.3 67.11,141.88 ; SWGQ.3 68.2,142.98 ; 61.11,48.92 H3.9 ; H3.9 62.15,49.96 ; H3.9 63.2,48.92 ; H3.9 62.15,47.88 ; 118.15,111.16 H4.C14 ; H4.C14 118.96,111.97 ; H4.C14 117.34,111.97 ; H4.C14 118.15,112.79 ; 117.34,103.97 H4.C18 ; H4.C18 118.15,104.79 ; H4.C18 118.96,103.97 ; H4.C18 118.15,103.16 ; SWGQ.5 70.74,142.98 ; SWGQ.5 71.83,141.88 ; SWGQ.5 70.74,140.79 ; SWGQ.5 69.65,141.88 ; H4.C11 118.15,118.79 ; H4.C11 117.34,117.97 ; H4.C11 118.15,117.16 ; H4.C11 118.96,117.97 ; SMA_CLK.3 79.43,81.66 ; SMA_CLK.3 78.28,82.8 ; SMA_CLK.3 77.14,81.66 ; SMA_CLK.3 78.28,80.52 ; SWGI.5 94.87,142.98 ; SWGI.5 93.78,141.88 ; SWGI.5 95.96,141.88 ; SWGI.5 94.87,140.79 ; 117.34,99.97 H4.C20 ; H4.C20 118.96,99.97 ; H4.C20 118.15,100.79 ; H4.C20 118.15,99.16 ; 116.15,127.16 H4.D6 ; H4.D6 116.15,128.79 ; H4.D6 116.96,127.97 ; H4.D6 115.34,127.97 ; SWGI.13 105.03,142.98 ; SWGI.13 106.12,141.88 ; SWGI.13 103.94,141.88 ; SWGI.13 105.03,140.79 ; 73.28,140.79 SWGQ.7 ; SWGQ.7 74.37,141.88 ; SWGQ.7 73.28,142.98 ; SWGQ.7 72.19,141.88 ; H4.C23 118.15,94.79 ; H4.C23 118.15,93.16 ; H4.C23 117.34,93.97 ; H4.C23 118.96,93.97 ; 117.34,123.97 H4.C8 ; H4.C8 118.15,123.16 ; H4.C8 118.96,123.97 ; H4.C8 118.15,124.79 ; H4.C12 118.15,116.79 ; H4.C12 118.15,115.16 ; H4.C12 117.34,115.97 ; H4.C12 118.96,115.97 ; SWGI.11 103.58,141.88 ; SWGI.11 101.4,141.88 ; SWGI.11 102.49,140.79 ; SWGI.11 102.49,142.98 ; 116.15,131.16 H4.D4 ; H4.D4 116.15,132.79 ; H4.D4 116.96,131.97 ; H4.D4 115.34,131.97 ; 82.22,76.58 SMA_CLK.5 ; SMA_CLK.5 83.36,75.44 ; SMA_CLK.5 83.36,77.72 ; SMA_CLK.5 84.51,76.58 ; H4.D11 116.96,117.97 ; H4.D11 116.15,118.79 ; H4.D11 116.15,117.16 ; H4.D11 115.34,117.97 ; H4.C21 118.96,97.97 ; H4.C21 117.34,97.97 ; H4.C21 118.15,98.79 ; H4.C21 118.15,97.16 ; 74.73,141.88 SWGQ.9 ; SWGQ.9 75.82,142.98 ; SWGQ.9 76.91,141.88 ; SWGQ.9 75.82,140.79 ; H4.A3 122.96,133.97 ; H4.A3 122.15,134.79 ; H4.A3 122.15,133.16 ; H4.A3 121.34,133.97 ; 82.35,141.88 SWGQ.15 ; SWGQ.15 83.44,142.98 ; SWGQ.15 83.44,140.79 ; SWGQ.15 84.53,141.88 ; 65.15,21.44 JP10.1 ; JP10.1 67.69,21.44 ; JP10.1 66.42,22.71 ; 116.15,125.16 H4.D7 ; H4.D7 116.15,126.79 ; H4.D7 116.96,125.97 ; H4.D7 115.34,125.97 ; SMA_REF.5 110.67,43.92 ; SMA_REF.5 111.81,42.77 ; SMA_REF.5 109.52,42.77 ; SMA_REF.5 110.67,41.63 ; 56.92,148.62 MH1.1 ; MH1.1 62.97,148.62 ; MH1.1 59.94,151.64 ; MH1.1 59.94,145.59 ; H4.B22 120.96,95.97 ; H4.B22 120.15,96.79 ; H4.B22 119.34,95.97 ; H4.B22 120.15,95.16 ; SMA_CLK.4 78.28,77.72 ; SMA_CLK.4 77.14,76.58 ; SMA_CLK.4 78.28,75.44 ; SMA_CLK.4 79.43,76.58 ; SWGI.1 90.88,141.88 ; SWGI.1 89.79,142.98 ; SWGI.1 88.7,141.88 ; SWGI.1 89.79,140.79 ; 65.66,140.79 SWGQ.1 ; SWGQ.1 65.66,142.98 ; SWGQ.1 66.75,141.88 ; SWGQ.1 64.57,141.88 ; 80.9,140.79 SWGQ.13 ; SWGQ.13 81.99,141.88 ; SWGQ.13 80.9,142.98 ; SWGQ.13 79.81,141.88 ; H4.A22 122.96,95.97 ; H4.A22 122.15,96.79 ; H4.A22 121.34,95.97 ; H4.A22 122.15,95.16 ; JP11.1 105.54,84.35 ; JP11.1 103,84.35 ; JP11.1 104.27,85.62
  GROUND_L3 w0.406: H4.C13 118.15,114.79 ; H4.C13 118.96,113.97 ; H4.C13 118.15,113.16 ; H4.C13 117.34,113.97 ; H4.C20 118.96,99.97 ; H4.C20 118.15,99.16 ; H4.C20 117.34,99.97 ; H4.C20 118.15,100.79 ; 122.81,145.59 MH2.1 ; MH2.1 119.79,148.62 ; MH2.1 125.83,148.62 ; MH2.1 122.81,151.64 ; H4.C6 118.96,127.97 ; H4.C6 117.34,127.97 ; H4.C6 118.15,127.16 ; H4.C6 118.15,128.79 ; 57.05,112.7 TP2.1 ; TP2.1 58.5,114.15 ; TP2.1 57.05,115.6 ; TP2.1 55.6,114.15 ; 120.17,56.39 TP1.1 ; TP1.1 121.62,54.94 ; TP1.1 123.06,56.39 ; TP1.1 121.62,57.84 ; SWGQ.7 73.28,142.98 ; SWGQ.7 72.19,141.88 ; SWGQ.7 74.37,141.88 ; SWGQ.7 73.28,140.79 ; POWER.2 48.84,13.11 ; POWER.2 47.35,11.61 ; POWER.2 47.35,14.61 ; POWER.2 45.85,13.11 ; 117.34,91.97 H4.C24 ; H4.C24 118.96,91.97 ; H4.C24 118.15,91.16 ; H4.C24 118.15,92.79 ; H4.C8 118.15,124.79 ; H4.C8 117.34,123.97 ; H4.C8 118.96,123.97 ; H4.C8 118.15,123.16 ; H4.C17 118.15,106.79 ; H4.C17 118.96,105.97 ; H4.C17 117.34,105.97 ; H4.C17 118.15,105.16 ; SWGQ.11 79.45,141.88 ; SWGQ.11 78.36,140.79 ; SWGQ.11 77.27,141.88 ; SWGQ.11 78.36,142.98 ; H4.D7 116.15,126.79 ; H4.D7 115.34,125.97 ; H4.D7 116.15,125.16 ; H4.D7 116.96,125.97 ; MH4.1 122.81,11.94 ; MH4.1 122.81,5.89 ; MH4.1 125.83,8.92 ; MH4.1 119.79,8.92 ; SWGQ.5 70.74,142.98 ; SWGQ.5 69.65,141.88 ; SWGQ.5 71.83,141.88 ; SWGQ.5 70.74,140.79 ; 118.15,137.16 H4.C1 ; H4.C1 118.96,137.97 ; H4.C1 117.34,137.97 ; H4.C1 118.15,138.79 ; H4.D6 116.15,128.79 ; H4.D6 115.34,127.97 ; H4.D6 116.15,127.16 ; H4.D6 116.96,127.97 ; SWGI.1 90.88,141.88 ; SWGI.1 89.79,140.79 ; SWGI.1 89.79,142.98 ; SWGI.1 88.7,141.88 ; SMA_REF.3 105.59,49 ; SMA_REF.3 105.59,46.71 ; SMA_REF.3 104.44,47.85 ; SMA_REF.3 106.73,47.85 ; 118.15,121.16 H4.C9 ; H4.C9 118.96,121.97 ; H4.C9 118.15,122.79 ; H4.C9 117.34,121.97 ; JP10.1 67.69,21.44 ; JP10.1 66.42,22.71 ; JP10.1 65.15,21.44 ; 83.36,80.52 SMA_CLK.2 ; SMA_CLK.2 84.51,81.66 ; SMA_CLK.2 83.36,82.8 ; SMA_CLK.2 82.22,81.66 ; H4.C23 118.96,93.97 ; H4.C23 117.34,93.97 ; H4.C23 118.15,93.16 ; H4.C23 118.15,94.79 ; 67.11,141.88 SWGQ.3 ; SWGQ.3 68.2,140.79 ; SWGQ.3 68.2,142.98 ; SWGQ.3 69.29,141.88 ; 61.11,48.92 H3.9 ; H3.9 63.2,48.92 ; H3.9 62.15,47.88 ; H3.9 62.15,49.96 ; 118.15,131.16 H4.C4 ; H4.C4 118.96,131.97 ; H4.C4 117.34,131.97 ; H4.C4 118.15,132.79 ; 116.15,131.16 H4.D4 ; H4.D4 115.34,131.97 ; H4.D4 116.15,132.79 ; H4.D4 116.96,131.97 ; 80.9,140.79 SWGQ.13 ; SWGQ.13 81.99,141.88 ; SWGQ.13 79.81,141.88 ; SWGQ.13 80.9,142.98 ; 10.57,81.31 MH5.1 ; MH5.1 16.61,81.31 ; MH5.1 13.59,78.28 ; MH5.1 13.59,84.33 ; H4.D1 116.96,137.97 ; H4.D1 116.15,138.79 ; H4.D1 115.34,137.97 ; H4.D1 116.15,137.16 ; 118.15,117.16 H4.C11 ; H4.C11 118.96,117.97 ; H4.C11 117.34,117.97 ; H4.C11 118.15,118.79 ; 115.34,123.97 H4.D8 ; H4.D8 116.15,123.16 ; H4.D8 116.96,123.97 ; H4.D8 116.15,124.79 ; TP4.1 105.61,38.96 ; TP4.1 105.61,36.07 ; TP4.1 104.16,37.52 ; TP4.1 107.06,37.52 ; JP11.1 105.54,84.35 ; JP11.1 103,84.35 ; JP11.1 104.27,85.62 ; H4.A3 122.15,134.79 ; H4.A3 122.96,133.97 ; H4.A3 122.15,133.16 ; H4.A3 121.34,133.97 ; SMA_CLK.4 79.43,76.58 ; SMA_CLK.4 78.28,75.44 ; SMA_CLK.4 78.28,77.72 ; SMA_CLK.4 77.14,76.58 ; 117.34,119.97 H4.C10 ; H4.C10 118.15,120.79 ; H4.C10 118.15,119.16 ; H4.C10 118.96,119.97 ; SWGI.15 107.57,142.98 ; SWGI.15 108.66,141.88 ; SWGI.15 107.57,140.79 ; SWGI.15 106.48,141.88 ; 96.32,141.88 SWGI.7 ; SWGI.7 97.41,142.98 ; SWGI.7 98.5,141.88 ; SWGI.7 97.41,140.79 ; 117.34,125.97 H4.C7 ; H4.C7 118.15,125.16 ; H4.C7 118.96,125.97 ; H4.C7 118.15,126.79 ; 103.94,141.88 SWGI.13 ; SWGI.13 105.03,142.98 ; SWGI.13 106.12,141.88 ; SWGI.13 105.03,140.79 ; H4.C21 118.15,98.79 ; H4.C21 117.34,97.97 ; H4.C21 118.96,97.97 ; H4.C21 118.15,97.16 ; 118.15,111.16 H4.C14 ; H4.C14 118.96,111.97 ; H4.C14 118.15,112.79 ; H4.C14 117.34,111.97 ; 116.15,119.16 H4.D10 ; H4.D10 116.15,120.79 ; H4.D10 116.96,119.97 ; H4.D10 115.34,119.97 ; H4.B22 120.15,96.79 ; H4.B22 119.34,95.97 ; H4.B22 120.96,95.97 ; H4.B22 120.15,95.16 ; 118.15,135.16 H4.C2 ; H4.C2 118.96,135.97 ; H4.C2 117.34,135.97 ; H4.C2 118.15,136.79 ; H4.A22 122.96,95.97 ; H4.A22 122.15,96.79 ; H4.A22 121.34,95.97 ; H4.A22 122.15,95.16 ; SMA_REF.2 111.81,47.85 ; SMA_REF.2 110.67,46.71 ; SMA_REF.2 109.52,47.85 ; SMA_REF.2 110.67,49 ; H4.D14 116.15,112.79 ; H4.D14 115.34,111.97 ; H4.D14 116.96,111.97 ; H4.D14 116.15,111.16 ; 117.34,107.97 H4.C16 ; H4.C16 118.15,108.79 ; H4.C16 118.15,107.16 ; H4.C16 118.96,107.97 ; 118.15,115.16 H4.C12 ; H4.C12 117.34,115.97 ; H4.C12 118.96,115.97 ; H4.C12 118.15,116.79 ; H4.C15 118.96,109.97 ; H4.C15 118.15,109.16 ; H4.C15 117.34,109.97 ; H4.C15 118.15,110.79 ; 101.4,141.88 SWGI.11 ; SWGI.11 102.49,140.79 ; SWGI.11 102.49,142.98 ; SWGI.11 103.58,141.88 ; H4.C5 118.15,130.79 ; H4.C5 117.34,129.97 ; H4.C5 118.96,129.97 ; H4.C5 118.15,129.16 ; 117.34,101.97 H4.C19 ; H4.C19 118.96,101.97 ; H4.C19 118.15,101.16 ; H4.C19 118.15,102.79 ; SWGI.5 94.87,142.98 ; SWGI.5 95.96,141.88 ; SWGI.5 93.78,141.88 ; SWGI.5 94.87,140.79 ; SWGI.9 99.95,142.98 ; SWGI.9 98.86,141.88 ; SWGI.9 101.04,141.88 ; SWGI.9 99.95,140.79 ; H4.D5 116.15,130.79 ; H4.D5 116.96,129.97 ; H4.D5 116.15,129.16 ; H4.D5 115.34,129.97 ; H4.D11 116.15,118.79 ; H4.D11 116.96,117.97 ; H4.D11 115.34,117.97 ; H4.D11 116.15,117.16 ; MH3.1 13.59,11.94 ; MH3.1 13.59,5.89 ; MH3.1 10.57,8.92 ; MH3.1 16.61,8.92 ; H4.C22 118.96,95.97 ; H4.C22 118.15,96.79 ; H4.C22 117.34,95.97 ; H4.C22 118.15,95.16 ; 77.04,69.14 TP3.1 ; TP3.1 79.93,69.14 ; TP3.1 78.49,67.69 ; TP3.1 78.49,70.59 ; SMA_REF.5 111.81,42.77 ; SMA_REF.5 110.67,41.63 ; SMA_REF.5 110.67,43.92 ; SMA_REF.5 109.52,42.77 ; 83.44,140.79 SWGQ.15 ; SWGQ.15 83.44,142.98 ; SWGQ.15 82.35,141.88 ; SWGQ.15 84.53,141.88 ; 75.82,140.79 SWGQ.9 ; SWGQ.9 76.91,141.88 ; SWGQ.9 75.82,142.98 ; SWGQ.9 74.73,141.88 ; H4.D15 116.15,110.79 ; H4.D15 116.15,109.16 ; H4.D15 115.34,109.97 ; H4.D15 116.96,109.97 ; H4.D16 116.15,108.79 ; H4.D16 115.34,107.97 ; H4.D16 116.96,107.97 ; H4.D16 116.15,107.16 ; MH1.1 59.94,151.64 ; MH1.1 59.94,145.59 ; MH1.1 56.92,148.62 ; MH1.1 62.97,148.62 ; SWGQ.1 65.66,142.98 ; SWGQ.1 64.57,141.88 ; SWGQ.1 66.75,141.88 ; SWGQ.1 65.66,140.79 ; 83.36,75.44 SMA_CLK.5 ; SMA_CLK.5 84.51,76.58 ; SMA_CLK.5 82.22,76.58 ; SMA_CLK.5 83.36,77.72 ; SMA_CLK.3 79.43,81.66 ; SMA_CLK.3 78.28,80.52 ; SMA_CLK.3 78.28,82.8 ; SMA_CLK.3 77.14,81.66 ; H4.D9 116.15,122.79 ; H4.D9 116.96,121.97 ; H4.D9 115.34,121.97 ; H4.D9 116.15,121.16 ; SMA_REF.4 106.73,42.77 ; SMA_REF.4 105.59,43.92 ; SMA_REF.4 104.44,42.77 ; SMA_REF.4 105.59,41.63 ; JP10.2 67.69,18.9 ; JP10.2 65.15,18.9 ; JP10.2 66.42,17.63 ; 103,81.81 JP11.2 ; JP11.2 104.27,80.54 ; JP11.2 105.54,81.81 ; H4.C18 118.96,103.97 ; H4.C18 117.34,103.97 ; H4.C18 118.15,104.79 ; H4.C18 118.15,103.16 ; SWGI.3 92.33,142.98 ; SWGI.3 91.24,141.88 ; SWGI.3 93.42,141.88 ; SWGI.3 92.33,140.79
  POWER_L4 w0.406: 118.15,131.03 H4.C4 ; H4.C4 117.21,131.97 ; H4.C4 119.09,131.97 ; H4.C4 118.15,132.91 ; H4.C24 118.15,92.91 ; H4.C24 117.21,91.97 ; H4.C24 118.15,91.03 ; H4.D15 117.09,109.97 ; H4.D15 116.15,110.91 ; H4.D15 115.21,109.97 ; H4.D15 116.15,109.03 ; 121.21,133.97 H4.A3 ; H4.A3 122.15,133.03 ; H4.A3 123.09,133.97 ; H4.A3 122.15,134.91 ; 118.15,125.03 H4.C7 ; H4.C7 118.15,126.91 ; H4.C7 119.09,125.97 ; H4.C7 117.21,125.97 ; 118.15,117.03 H4.C11 ; H4.C11 119.09,117.97 ; H4.C11 118.15,118.91 ; H4.C11 117.21,117.97 ; H4.D11 116.15,118.91 ; H4.D11 117.09,117.97 ; H4.D11 116.15,117.03 ; H4.D11 115.21,117.97 ; 117.21,93.97 H4.C23 118.15,93.03 ; 116.15,125.03 H4.D7 ; H4.D7 115.21,125.97 ; H4.D7 116.15,126.91 ; H4.D7 117.09,125.97 ; 116.15,123.03 H4.D8 ; H4.D8 115.21,123.97 ; H4.D8 117.09,123.97 ; H4.D8 116.15,124.91 ; 118.15,137.03 H4.C1 ; H4.C1 119.09,137.97 ; H4.C1 117.21,137.97 ; H4.C1 118.15,138.91 ; H4.C2 119.09,135.97 ; H4.C2 118.15,136.91 ; H4.C2 117.21,135.97 ; H4.C2 118.15,135.03 ; 117.21,115.97 H4.C12 ; H4.C12 118.15,115.03 ; H4.C12 119.09,115.97 ; H4.C12 118.15,116.91 ; H4.C10 119.09,119.97 ; H4.C10 118.15,120.91 ; H4.C10 118.15,119.03 ; H4.C10 117.21,119.97 ; H4.C15 118.15,110.91 ; H4.C15 118.15,109.03 ; H4.C15 119.09,109.97 ; H4.C15 117.21,109.97 ; H4.C16 118.15,108.91 ; H4.C16 118.15,107.03 ; H4.C16 119.09,107.97 ; H4.C16 117.21,107.97 ; JP11.1 104.27,85.75 ; JP11.1 105.66,84.35 ; JP11.1 102.87,84.35 ; 62.15,47.75 H3.9 ; H3.9 63.32,48.92 ; H3.9 62.15,50.09 ; H3.9 60.98,48.92 ; 115.21,119.97 H4.D10 ; H4.D10 117.09,119.97 ; H4.D10 116.15,119.03 ; H4.D10 116.15,120.91 ; H4.C9 119.09,121.97 ; H4.C9 117.21,121.97 ; H4.C9 118.15,121.03 ; H4.C9 118.15,122.91 ; H4.D4 116.15,132.91 ; H4.D4 115.21,131.97 ; H4.D4 117.09,131.97 ; H4.D4 116.15,131.03 ; MH2.1 125.96,148.62 ; MH2.1 122.81,151.77 ; MH2.1 119.66,148.62 ; MH2.1 122.81,145.47 ; 115.21,107.97 H4.D16 ; H4.D16 116.15,108.91 ; H4.D16 116.15,107.03 ; H4.D16 117.09,107.97 ; 118.15,129.03 H4.C5 ; H4.C5 117.21,129.97 ; H4.C5 118.15,130.91 ; H4.C5 119.09,129.97 ; H4.D6 117.09,127.97 ; H4.D6 116.15,128.91 ; H4.D6 116.15,127.03 ; H4.D6 115.21,127.97 ; 117.21,103.97 H4.C18 ; H4.C18 119.09,103.97 ; H4.C18 118.15,104.91 ; H4.C18 118.15,103.03 ; 115.21,121.97 H4.D9 ; H4.D9 117.09,121.97 ; H4.D9 116.15,121.03 ; H4.D9 116.15,122.91 ; H4.C6 118.15,128.91 ; H4.C6 117.21,127.97 ; H4.C6 118.15,127.03 ; H4.C6 119.09,127.97 ; 118.15,101.03 H4.C19 ; H4.C19 117.21,101.97 ; H4.C19 118.15,102.91 ; H4.C19 119.09,101.97 ; 117.21,123.97 H4.C8 ; H4.C8 119.09,123.97 ; H4.C8 118.15,123.03 ; H4.C8 118.15,124.91 ; 115.21,111.97 H4.D14 ; H4.D14 116.15,112.91 ; H4.D14 117.09,111.97 ; H4.D14 116.15,111.03 ; 13.59,78.16 MH5.1 ; MH5.1 16.74,81.31 ; MH5.1 13.59,84.46 ; MH5.1 10.44,81.31 ; H4.C17 119.09,105.97 ; H4.C17 118.15,105.03 ; H4.C17 118.15,106.91 ; H4.C17 117.21,105.97 ; 102.87,81.81 JP11.2 ; JP11.2 104.27,80.42 ; JP11.2 105.66,81.81 ; 117.21,97.97 H4.C21 118.15,98.91 ; H4.C14 119.09,111.97 ; H4.C14 117.21,111.97 ; H4.C14 118.15,111.03 ; H4.C14 118.15,112.91 ; 65.02,21.44 JP10.1 ; JP10.1 67.82,21.44 ; JP10.1 66.42,22.84 ; H4.D1 117.09,137.97 ; H4.D1 116.15,137.03 ; H4.D1 116.15,138.91 ; H4.D1 115.21,137.97 ; H4.C13 119.09,113.97 ; H4.C13 118.15,114.91 ; H4.C13 117.21,113.97 ; H4.C13 118.15,113.03 ; H4.C20 119.09,99.97 ; H4.C20 117.21,99.97 ; H4.C20 118.15,100.91 ; H4.C20 118.15,99.03 ; 116.15,129.03 H4.D5 ; H4.D5 116.15,130.91 ; H4.D5 115.21,129.97 ; H4.D5 117.09,129.97
  GROUND_L5 w0.406: 55.6,114.15 TP2.1 ; TP2.1 57.05,115.6 ; TP2.1 58.5,114.15 ; TP2.1 57.05,112.7 ; H4.D9 116.15,122.79 ; H4.D9 116.15,121.16 ; H4.D9 115.34,121.97 ; H4.D9 116.96,121.97 ; H4.C2 118.15,136.79 ; H4.C2 118.15,135.16 ; H4.C2 118.96,135.97 ; H4.C2 117.34,135.97 ; 115.34,137.97 H4.D1 ; H4.D1 116.15,138.79 ; H4.D1 116.15,137.16 ; H4.D1 116.96,137.97 ; SWGI.3 92.33,142.98 ; SWGI.3 92.33,140.79 ; SWGI.3 91.24,141.88 ; SWGI.3 93.42,141.88 ; SWGI.5 95.96,141.88 ; SWGI.5 94.87,142.98 ; SWGI.5 93.78,141.88 ; SWGI.5 94.87,140.79 ; MH1.1 62.97,148.62 ; MH1.1 59.94,151.64 ; MH1.1 56.92,148.62 ; MH1.1 59.94,145.59 ; H4.C19 118.15,102.79 ; H4.C19 118.96,101.97 ; H4.C19 117.34,101.97 ; H4.C19 118.15,101.16 ; 83.36,80.52 SMA_CLK.2 ; SMA_CLK.2 83.36,82.8 ; SMA_CLK.2 82.22,81.66 ; SMA_CLK.2 84.51,81.66 ; 80.9,140.79 SWGQ.13 ; SWGQ.13 79.81,141.88 ; SWGQ.13 80.9,142.98 ; SWGQ.13 81.99,141.88 ; H4.C16 118.96,107.97 ; H4.C16 118.15,108.79 ; H4.C16 118.15,107.16 ; H4.C16 117.34,107.97 ; 78.28,75.44 SMA_CLK.4 ; SMA_CLK.4 77.14,76.58 ; SMA_CLK.4 78.28,77.72 ; SMA_CLK.4 79.43,76.58 ; SMA_REF.2 111.81,47.85 ; SMA_REF.2 110.67,49 ; SMA_REF.2 109.52,47.85 ; SMA_REF.2 110.67,46.71 ; 118.15,99.16 H4.C20 ; H4.C20 117.34,99.97 ; H4.C20 118.15,100.79 ; H4.C20 118.96,99.97 ; 45.85,13.11 POWER.2 ; POWER.2 47.35,14.61 ; POWER.2 47.35,11.61 ; POWER.2 48.84,13.11 ; H4.D4 116.96,131.97 ; H4.D4 115.34,131.97 ; H4.D4 116.15,132.79 ; H4.D4 116.15,131.16 ; TP1.1 121.62,57.84 ; TP1.1 120.17,56.39 ; TP1.1 123.06,56.39 ; TP1.1 121.62,54.94 ; SWGQ.5 70.74,142.98 ; SWGQ.5 70.74,140.79 ; SWGQ.5 71.83,141.88 ; SWGQ.5 69.65,141.88 ; SWGQ.9 76.91,141.88 ; SWGQ.9 75.82,140.79 ; SWGQ.9 75.82,142.98 ; SWGQ.9 74.73,141.88 ; 118.15,105.16 H4.C17 ; H4.C17 118.15,106.79 ; H4.C17 118.96,105.97 ; H4.C17 117.34,105.97 ; 104.44,42.77 SMA_REF.4 ; SMA_REF.4 106.73,42.77 ; SMA_REF.4 105.59,41.63 ; SMA_REF.4 105.59,43.92 ; 118.15,97.16 H4.C21 ; H4.C21 118.15,98.79 ; H4.C21 117.34,97.97 ; H4.C21 118.96,97.97 ; H4.D11 116.96,117.97 ; H4.D11 115.34,117.97 ; H4.D11 116.15,117.16 ; H4.D11 116.15,118.79 ; H4.A22 122.96,95.97 ; H4.A22 121.34,95.97 ; H4.A22 122.15,96.79 ; H4.A22 122.15,95.16 ; TP4.1 105.61,38.96 ; TP4.1 105.61,36.07 ; TP4.1 107.06,37.52 ; TP4.1 104.16,37.52 ; 83.36,75.44 SMA_CLK.5 ; SMA_CLK.5 83.36,77.72 ; SMA_CLK.5 84.51,76.58 ; SMA_CLK.5 82.22,76.58 ; 110.67,41.63 SMA_REF.5 ; SMA_REF.5 111.81,42.77 ; SMA_REF.5 109.52,42.77 ; SMA_REF.5 110.67,43.92 ; 118.15,111.16 H4.C14 ; H4.C14 118.96,111.97 ; H4.C14 118.15,112.79 ; H4.C14 117.34,111.97 ; H4.C15 118.96,109.97 ; H4.C15 118.15,110.79 ; H4.C15 117.34,109.97 ; H4.C15 118.15,109.16 ; H4.C22 118.96,95.97 ; H4.C22 117.34,95.97 ; H4.C22 118.15,96.79 ; H4.C22 118.15,95.16 ; TP3.1 78.49,70.59 ; TP3.1 78.49,67.69 ; TP3.1 77.04,69.14 ; TP3.1 79.93,69.14 ; H4.D15 116.96,109.97 ; H4.D15 116.15,110.79 ; H4.D15 116.15,109.16 ; H4.D15 115.34,109.97 ; H4.C4 118.96,131.97 ; H4.C4 118.15,131.16 ; H4.C4 118.15,132.79 ; H4.C4 117.34,131.97 ; H4.C11 118.96,117.97 ; H4.C11 118.15,118.79 ; H4.C11 118.15,117.16 ; H4.C11 117.34,117.97 ; 118.15,103.16 H4.C18 ; H4.C18 117.34,103.97 ; H4.C18 118.96,103.97 ; H4.C18 118.15,104.79 ; 118.15,137.16 H4.C1 ; H4.C1 118.15,138.79 ; H4.C1 117.34,137.97 ; H4.C1 118.96,137.97 ; H4.C10 118.96,119.97 ; H4.C10 118.15,119.16 ; H4.C10 117.34,119.97 ; H4.C10 118.15,120.79 ; 115.34,125.97 H4.D7 ; H4.D7 116.15,126.79 ; H4.D7 116.15,125.16 ; H4.D7 116.96,125.97 ; 72.19,141.88 SWGQ.7 ; SWGQ.7 73.28,140.79 ; SWGQ.7 74.37,141.88 ; SWGQ.7 73.28,142.98 ; 88.7,141.88 SWGI.1 ; SWGI.1 89.79,142.98 ; SWGI.1 90.88,141.88 ; SWGI.1 89.79,140.79 ; 118.15,127.16 H4.C6 ; H4.C6 117.34,127.97 ; H4.C6 118.15,128.79 ; H4.C6 118.96,127.97 ; SWGQ.11 78.36,142.98 ; SWGQ.11 78.36,140.79 ; SWGQ.11 77.27,141.88 ; SWGQ.11 79.45,141.88 ; H4.C5 118.15,130.79 ; H4.C5 118.15,129.16 ; H4.C5 118.96,129.97 ; H4.C5 117.34,129.97 ; SMA_REF.3 106.73,47.85 ; SMA_REF.3 105.59,49 ; SMA_REF.3 104.44,47.85 ; SMA_REF.3 105.59,46.71 ; H4.C24 118.15,92.79 ; H4.C24 118.96,91.97 ; H4.C24 118.15,91.16 ; H4.C24 117.34,91.97 ; H4.C12 118.96,115.97 ; H4.C12 118.15,115.16 ; H4.C12 118.15,116.79 ; H4.C12 117.34,115.97 ; MH3.1 13.59,11.94 ; MH3.1 16.61,8.92 ; MH3.1 13.59,5.89 ; MH3.1 10.57,8.92 ; 98.86,141.88 SWGI.9 ; SWGI.9 99.95,140.79 ; SWGI.9 99.95,142.98 ; SWGI.9 101.04,141.88 ; H4.C7 118.15,126.79 ; H4.C7 118.96,125.97 ; H4.C7 118.15,125.16 ; H4.C7 117.34,125.97 ; H4.C13 118.15,114.79 ; H4.C13 118.15,113.16 ; H4.C13 117.34,113.97 ; H4.C13 118.96,113.97 ; H4.C23 118.15,94.79 ; H4.C23 118.15,93.16 ; H4.C23 118.96,93.97 ; H4.C23 117.34,93.97 ; 61.11,48.92 H3.9 ; H3.9 62.15,49.96 ; H3.9 63.2,48.92 ; H3.9 62.15,47.88 ; H4.B22 120.15,96.79 ; H4.B22 120.96,95.97 ; H4.B22 120.15,95.16 ; H4.B22 119.34,95.97 ; 64.57,141.88 SWGQ.1 ; SWGQ.1 66.75,141.88 ; SWGQ.1 65.66,140.79 ; SWGQ.1 65.66,142.98 ; H4.D10 116.96,119.97 ; H4.D10 115.34,119.97 ; H4.D10 116.15,120.79 ; H4.D10 116.15,119.16 ; H4.D14 116.15,112.79 ; H4.D14 116.96,111.97 ; H4.D14 116.15,111.16 ; H4.D14 115.34,111.97 ; 115.34,129.97 H4.D5 ; H4.D5 116.15,130.79 ; H4.D5 116.96,129.97 ; H4.D5 116.15,129.16 ; 78.28,80.52 SMA_CLK.3 ; SMA_CLK.3 78.28,82.8 ; SMA_CLK.3 79.43,81.66 ; SMA_CLK.3 77.14,81.66 ; JP10.1 66.42,22.71 ; JP10.1 67.69,21.44 ; JP10.1 65.15,21.44 ; MH5.1 13.59,84.33 ; MH5.1 13.59,78.28 ; MH5.1 16.61,81.31 ; MH5.1 10.57,81.31 ; SWGI.7 97.41,142.98 ; SWGI.7 97.41,140.79 ; SWGI.7 96.32,141.88 ; SWGI.7 98.5,141.88 ; 122.15,133.16 H4.A3 ; H4.A3 122.15,134.79 ; H4.A3 122.96,133.97 ; H4.A3 121.34,133.97 ; SWGI.11 102.49,142.98 ; SWGI.11 101.4,141.88 ; SWGI.11 102.49,140.79 ; SWGI.11 103.58,141.88 ; 115.34,107.97 H4.D16 ; H4.D16 116.96,107.97 ; H4.D16 116.15,108.79 ; H4.D16 116.15,107.16 ; MH2.1 122.81,151.64 ; MH2.1 125.83,148.62 ; MH2.1 122.81,145.59 ; MH2.1 119.79,148.62 ; 116.15,127.16 H4.D6 ; H4.D6 116.15,128.79 ; H4.D6 116.96,127.97 ; H4.D6 115.34,127.97 ; JP11.2 105.54,81.81 ; JP11.2 103,81.81 ; JP11.2 104.27,80.54 ; 65.15,18.9 JP10.2 ; JP10.2 66.42,17.63 ; JP10.2 67.69,18.9 ; 117.34,123.97 H4.C8 ; H4.C8 118.15,123.16 ; H4.C8 118.96,123.97 ; H4.C8 118.15,124.79 ; H4.C9 118.15,122.79 ; H4.C9 117.34,121.97 ; H4.C9 118.96,121.97 ; H4.C9 118.15,121.16 ; 107.57,140.79 SWGI.15 ; SWGI.15 107.57,142.98 ; SWGI.15 106.48,141.88 ; SWGI.15 108.66,141.88 ; JP11.1 105.54,84.35 ; JP11.1 103,84.35 ; JP11.1 104.27,85.62 ; SWGQ.15 84.53,141.88 ; SWGQ.15 82.35,141.88 ; SWGQ.15 83.44,142.98 ; SWGQ.15 83.44,140.79 ; 68.2,140.79 SWGQ.3 ; SWGQ.3 69.29,141.88 ; SWGQ.3 67.11,141.88 ; SWGQ.3 68.2,142.98 ; 122.81,5.89 MH4.1 ; MH4.1 125.83,8.92 ; MH4.1 119.79,8.92 ; MH4.1 122.81,11.94 ; 115.34,123.97 H4.D8 ; H4.D8 116.15,123.16 ; H4.D8 116.96,123.97 ; H4.D8 116.15,124.79 ; SWGI.13 105.03,142.98 ; SWGI.13 103.94,141.88 ; SWGI.13 106.12,141.88 ; SWGI.13 105.03,140.79
  BOTTOM w0.203: v1(73.89,112.93) 74.14,112.67 C63.2 ; C64.2 75.16,112.85 v1(75.08,112.93) ; v1(73.89,115.32) 74.14,115.57 C61.2 ; C62.2 75.16,115.39 v1(75.08,115.32)
  BOTTOM w0.254: C165.1 116.94,70.92 v1(116.94,70.94)
  BOTTOM w0.343: 94.32,70.61 C106.1 ; C243.1 20.12,49.42 v1(20.93,50.23) 22.97,50.23 C241.1 ; C107.1 94.32,71.81 ; C261.1 22.97,32.8 v1(20.93,32.8) 20.93,31.37 C263.1 ; 93.83,72.19 94.34,72.69 C117.1
  BOTTOM w0.381: 89.79,143.03 SWGI.1 89.79,140.77 ; 92.33,143.03 SWGI.3 92.33,140.77 ; 83.44,143.03 SWGQ.15 83.44,140.77 ; 75.82,140.77 SWGQ.9 75.82,143.03 ; 91.97,115.16 C22.2 C21.2 92.02,116.64 C24.2 93.04,117.47 93.09,117.42 ; v1(93.79,116.6) 93.79,117.34 93.88,117.42 ; 91.97,111.35 C26.1 C27.1 91.85,110.11 C28.1 ; 91.97,111.35 C25.1 ; 91.97,111.35 92.01,111.39 v1(92.6,111.39) 92.79,111.2 C36.2 C35.2 93.6,110.95 v1(93.79,111.14) ; SWGQ.1 64.49,141.88 ; SWGQ.1 65.66,143.03 ; SWGQ.1 SWGQ.3 ; SWGQ.1 65.66,140.77 ; v1(93.79,113.53) 93.57,113.31 C29.2 92.81,113.31 v1(92.6,113.53) ; 93.88,117.42 C31.2 94.95,117.42 ; 93.88,117.42 C33.2 93.09,117.42 ; v1(92.6,114.72) 92.48,114.6 C30.2 ; SWGQ.5 70.74,143.03 ; SWGQ.5 70.74,140.77 ; SWGQ.5 SWGQ.3 ; 99.95,143.03 SWGI.9 99.95,141.38 99.29,140.72 ; 73.28,140.77 SWGQ.7 73.28,143.03 ; v1(92.6,116.6) 92.6,117.23 C34.2 93.09,117.42 ; 78.36,143.03 SWGQ.11 78.36,140.77 ; 107.57,143.03 SWGI.15 107.57,140.77 ; 101.52,140.72 102.49,141.68 SWGI.11 102.49,143.03 ; SWGQ.3 68.2,143.03 ; SWGQ.3 68.2,140.77 ; 105.03,143.03 SWGI.13 105.03,141.63 104.09,140.69 ; C142.1 v1(58.17,42.19) ; v1(96.18,117.11) 95.86,117.42 C32.2 94.95,117.42 ; 94.95,117.42 94.98,117.39 v1(94.98,116.6) v1(94.98,115.91) ; 97.41,140.77 SWGI.7 97.41,143.03 ; 80.9,143.03 SWGQ.13 80.9,140.77 ; 90.4,119.28 90.37,119.28 v1(90.37,119.2) ; 94.56,100.97 94.56,99.85 ; 94.87,143.03 SWGI.5 94.87,140.77
  BOTTOM w0.406: 84.28,94.17 U18.4 85.69,94.17 ; 76.96,81.66 SMA_CLK.3 ; SMA_CLK.3 79.6,81.66 ; SMA_CLK.3 78.28,80.34 ; SMA_CLK.3 78.28,82.98 ; 10.87,81.31 MH5.1 ; MH5.1 16.31,81.31 ; MH5.1 13.59,78.59 ; MH5.1 13.59,84.02 ; SMA_CLK.5 84.68,76.58 ; SMA_CLK.5 83.36,77.9 ; SMA_CLK.5 82.04,76.58 ; SMA_CLK.5 83.36,75.26 ; H4.D1 116.15,138.79 ; H4.D1 115.34,137.97 ; H4.D1 116.15,137.16 ; H4.D1 116.96,137.97 ; 120.42,56.39 TP1.1 ; TP1.1 122.81,56.39 ; TP1.1 121.62,55.19 ; TP1.1 121.62,57.58 ; 118.15,105.16 H4.C17 ; H4.C17 118.96,105.97 ; H4.C17 118.15,106.79 ; H4.C17 117.34,105.97 ; JP11.2 105.33,81.81 ; JP11.2 103.2,81.81 ; JP11.2 104.27,82.88 ; JP11.2 104.27,80.75 ; 117.34,101.97 H4.C19 ; H4.C19 118.96,101.97 ; H4.C19 118.15,101.16 ; H4.C19 118.15,102.79 ; 78.49,67.94 TP3.1 ; TP3.1 78.49,70.33 ; TP3.1 77.29,69.14 ; TP3.1 79.68,69.14 ; H4.A3 122.15,134.79 ; H4.A3 122.15,133.16 ; H4.A3 122.96,133.97 ; H4.A3 121.34,133.97 ; H4.C23 118.96,93.97 ; H4.C23 117.34,93.97 ; H4.C23 118.15,94.79 ; H4.C23 118.15,93.16 ; TP2.1 57.05,115.34 ; TP2.1 58.24,114.15 ; TP2.1 55.85,114.15 ; TP2.1 57.05,112.95 ; H4.C10 118.96,119.97 ; H4.C10 118.15,120.79 ; H4.C10 117.34,119.97 ; H4.C10 118.15,119.16 ; 93.9,69.72 v1(93.47,69.29) ; 92.76,67.87 C113.1 91.64,67.87 ; 73.42,113.59 R33.2 72.8,113.03 ; 94.95,67.87 C114.1 94.39,68.49 ; H4.D10 116.96,119.97 ; H4.D10 115.34,119.97 ; H4.D10 116.15,120.79 ; H4.D10 116.15,119.16 ; 20.01,50.23 v1(20.93,50.23) ; v1(20.93,50.23) 20.93,50.99 ; v1(20.93,50.23) 20.93,49.47 ; 117.34,111.97 H4.C14 ; H4.C14 118.15,112.79 ; H4.C14 118.96,111.97 ; H4.C14 118.15,111.16 ; H4.D6 116.15,128.79 ; H4.D6 116.96,127.97 ; H4.D6 115.34,127.97 ; H4.D6 116.15,127.16 ; v1(93.47,71.83) 93.09,72.21 C123.1 ; v1(93.47,71.83) 93.5,71.81 94.32,71.81 ; v1(93.47,71.83) 93.83,72.19 C128.1 ; 90.96,119.79 C23.2 91.52,119.28 ; H4.D15 116.15,110.79 ; H4.D15 115.34,109.97 ; H4.D15 116.15,109.16 ; H4.D15 116.96,109.97 ; H4.C18 118.96,103.97 ; H4.C18 118.15,104.79 ; H4.C18 117.34,103.97 ; H4.C18 118.15,103.16 ; H4.C2 118.96,135.97 ; H4.C2 118.15,136.79 ; H4.C2 117.34,135.97 ; H4.C2 118.15,135.16 ; SMA_REF.2 111.99,47.85 ; SMA_REF.2 110.67,46.53 ; SMA_REF.2 110.67,49.17 ; SMA_REF.2 109.35,47.85 ; 117.34,97.97 H4.C21 ; H4.C21 118.96,97.97 ; H4.C21 118.15,98.79 ; H4.C21 118.15,97.16 ; 104.27,47.85 SMA_REF.3 ; SMA_REF.3 105.59,46.53 ; SMA_REF.3 105.59,49.17 ; SMA_REF.3 106.91,47.85 ; C263.1 20.12,31.5 ; C263.1 v3(20.12,29.62) ; C263.1 21.18,30.56 ; C263.1 19.05,30.56 ; MH2.1 125.53,148.62 ; MH2.1 122.81,151.33 ; MH2.1 120.09,148.62 ; MH2.1 122.81,145.9 ; R216.2 23.85,58.9 ; R216.2 v3(23.23,58.34) ; R216.2 23.85,57.78 ; 23.85,40.36 R236.2 ; R236.2 23.85,41.48 ; R236.2 v3(23.23,40.92) ; H4.C5 118.96,129.97 ; H4.C5 117.34,129.97 ; H4.C5 118.15,130.79 ; H4.C5 118.15,129.16 ; 117.34,125.97 H4.C7 ; H4.C7 118.15,126.79 ; H4.C7 118.96,125.97 ; H4.C7 118.15,125.16 ; H4.C15 118.96,109.97 ; H4.C15 117.34,109.97 ; H4.C15 118.15,110.79 ; H4.C15 118.15,109.16 ; H4.C4 118.15,132.79 ; H4.C4 118.96,131.97 ; H4.C4 118.15,131.16 ; H4.C4 117.34,131.97 ; H4.B22 120.15,96.79 ; H4.B22 120.96,95.97 ; H4.B22 119.34,95.97 ; H4.B22 120.15,95.16 ; 104.27,42.77 SMA_REF.4 ; SMA_REF.4 105.59,44.09 ; SMA_REF.4 105.59,41.45 ; SMA_REF.4 106.91,42.77 ; H4.D4 116.15,132.79 ; H4.D4 116.15,131.16 ; H4.D4 116.96,131.97 ; H4.D4 115.34,131.97 ; 117.34,99.97 H4.C20 ; H4.C20 118.15,100.79 ; H4.C20 118.96,99.97 ; H4.C20 118.15,99.16 ; H4.D9 116.96,121.97 ; H4.D9 116.15,122.79 ; H4.D9 115.34,121.97 ; H4.D9 116.15,121.16 ; 109.35,42.77 SMA_REF.5 ; SMA_REF.5 110.67,41.45 ; SMA_REF.5 111.99,42.77 ; SMA_REF.5 110.67,44.09 ; 103.2,84.35 JP11.1 ; JP11.1 104.27,83.29 ; JP11.1 105.33,84.35 ; JP11.1 104.27,85.42 ; 65.35,21.44 JP10.1 ; JP10.1 67.49,21.44 ; JP10.1 66.42,22.5 ; JP10.1 66.42,20.37 ; 93.34,114.25 C29.2 93.34,112.37 ; 65.35,18.9 JP10.2 ; JP10.2 67.49,18.9 ; JP10.2 66.42,19.96 ; JP10.2 66.42,17.83 ; MH1.1 62.66,148.62 ; MH1.1 59.94,145.9 ; MH1.1 57.23,148.62 ; MH1.1 59.94,151.33 ; 13.59,6.2 MH3.1 ; MH3.1 16.31,8.92 ; MH3.1 10.87,8.92 ; MH3.1 13.59,11.63 ; 115.34,117.97 H4.D11 ; H4.D11 116.15,118.79 ; H4.D11 116.15,117.16 ; H4.D11 116.96,117.97 ; 117.34,137.97 H4.C1 ; H4.C1 118.15,138.79 ; H4.C1 118.96,137.97 ; H4.C1 118.15,137.16 ; H3.9 62.15,49.96 ; H3.9 62.15,47.88 ; H3.9 61.11,48.92 ; H3.9 63.2,48.92 ; H4.C6 118.96,127.97 ; H4.C6 118.15,127.16 ; H4.C6 118.15,128.79 ; H4.C6 117.34,127.97 ; 82.04,81.66 SMA_CLK.2 ; SMA_CLK.2 84.68,81.66 ; SMA_CLK.2 83.36,82.98 ; SMA_CLK.2 83.36,80.34 ; H4.D16 116.96,107.97 ; H4.D16 116.15,108.79 ; H4.D16 115.34,107.97 ; H4.D16 116.15,107.16 ; 118.15,115.16 H4.C12 ; H4.C12 117.34,115.97 ; H4.C12 118.96,115.97 ; H4.C12 118.15,116.79 ; H4.C8 118.15,124.79 ; H4.C8 118.96,123.97 ; H4.C8 118.15,123.16 ; H4.C8 117.34,123.97 ; H4.C24 118.96,91.97 ; H4.C24 118.15,92.79 ; H4.C24 117.34,91.97 ; H4.C24 118.15,91.16 ; H4.D5 116.15,130.79 ; H4.D5 116.15,129.16 ; H4.D5 116.96,129.97 ; H4.D5 115.34,129.97 ; H4.D14 116.15,112.79 ; H4.D14 116.15,111.16 ; H4.D14 116.96,111.97 ; H4.D14 115.34,111.97 ; 83.41,70.23 C131.2 82.35,69.29 ; H4.C11 118.15,118.79 ; H4.C11 117.34,117.97 ; H4.C11 118.15,117.16 ; H4.C11 118.96,117.97 ; 73.42,114.38 R32.2 72.8,114.94 ; 117.34,107.97 H4.C16 ; H4.C16 118.15,107.16 ; H4.C16 118.96,107.97 ; H4.C16 118.15,108.79 ; H4.A22 122.15,96.79 ; H4.A22 121.34,95.97 ; H4.A22 122.96,95.97 ; H4.A22 122.15,95.16 ; 94.32,70.61 93.52,70.61 v1(93.47,70.56) ; R234.1 v3(28.38,36.96) ; R234.1 v3(27.76,36.4) ; R234.1 v3(27.76,37.52) ; 79.77,22.86 R203.2 79.15,23.42 ; 23.11,49.15 C241.1 ; C241.1 v3(24.05,48.08) ; C241.1 24.05,50.22 ; C241.1 24.99,49.15 ; SMA_CLK.4 79.6,76.58 ; SMA_CLK.4 78.28,75.26 ; SMA_CLK.4 78.28,77.9 ; SMA_CLK.4 76.96,76.58 ; 115.34,125.97 H4.D7 ; H4.D7 116.96,125.97 ; H4.D7 116.15,126.79 ; H4.D7 116.15,125.16 ; 115.34,123.97 H4.D8 ; H4.D8 116.15,124.79 ; H4.D8 116.96,123.97 ; H4.D8 116.15,123.16 ; TP4.1 106.81,37.52 ; TP4.1 105.61,38.71 ; TP4.1 104.42,37.52 ; TP4.1 105.61,36.32 ; 57.53,42.75 C142.1 57.53,41.63 ; 20.01,32.8 v1(20.93,32.8) 20.93,33.57 ; C261.1 24.05,32.79 ; C261.1 v3(24.05,30.66) ; C261.1 23.11,31.72 ; C261.1 24.99,31.72 ; H4.C9 118.96,121.97 ; H4.C9 117.34,121.97 ; H4.C9 118.15,122.79 ; H4.C9 118.15,121.16 ; H4.C22 118.96,95.97 ; H4.C22 117.34,95.97 ; H4.C22 118.15,96.79 ; H4.C22 118.15,95.16 ; H4.C13 118.15,114.79 ; H4.C13 118.96,113.97 ; H4.C13 118.15,113.16 ; H4.C13 117.34,113.97 ; C124.1 92.33,71.96 v1(92.2,71.83) ; 94.59,99.9 C46.2 94.59,102.03 ; 47.35,11.81 POWER.2 ; POWER.2 47.35,14.4 ; POWER.2 46.05,13.11 ; POWER.2 48.64,13.11 ; v3(20.12,47.04) C243.1 ; C243.1 19.05,47.98 ; C243.1 21.18,47.98 ; MH4.1 125.53,8.92 ; MH4.1 120.09,8.92 ; MH4.1 122.81,11.63 ; MH4.1 122.81,6.2 ; C129.1 91.59,72.49 v1(90.93,71.83) ; 73.38,102.73 v1(73.38,103.35) ; v1(73.38,103.35) 73.94,103.35 ; v1(73.38,103.35) 72.82,103.35 ; 109.91,66.73 R140.2 111.02,66.73 ; 117.64,70.84 C165.1 117.02,70.28
  BOTTOM w0.508: v3(89.25,104.75) C85.1 C84.2 v3(90.58,103.42) ; v1(72.69,112.93) 72.72,112.93 72.72,113.59 R33.2 ; U12.2 v3(24.05,57.45) ; C171.1 97.28,84.43 v3(97.31,84.4) ; C76.2 92.74,123.11 ; C76.2 C77.2 ; C76.2 93.47,124 v3(93.24,124) ; R161.1 v3(97.21,85.24) ; v1(90.93,69.29) 90.86,69.37 C102.1 ; R203.2 v2(79.17,23.39) ; v3(110.95,66.7) 110.95,66.67 110.82,66.8 110.39,66.8 R140.2 v3(110.46,65.86) ; R214.1 v3(27.76,55.09) ; R214.1 v3(27.76,53.82) ; R214.1 28.4,54.46 v3(28.42,54.48) ; R32.2 72.72,114.38 72.72,115.32 v1(72.69,115.32) ; 82.37,71.32 v3(82.35,71.3) C131.2 v3(81.05,70.23) ; C86.2 92.63,105.13 ; C86.2 C87.2 ; C86.2 93.45,104.22 ; C165.1 v3(117.02,71.68) ; v3(102.06,56.74) R129.1 102.06,57.94 v3(102.26,58.14) C159.1 101.6,58.78 v3(101.52,58.7) ; v3(90.49,124.92) C75.1 v3(89.16,123.59) ; v3(110.46,73.1) R139.1 111.18,72.42 v3(111.25,72.34) ; C113.1 v1(92.2,69.29) ; U14.2 v1(24.05,39.9) ; C112.1 90.6,70.23 v1(90.93,70.56) ; C114.1 C104.1 93.52,69.24 v1(93.47,69.29) ; C116.1 93.9,69.72
  BOTTOM w0.635: U18.1 87.53,87.33 ; U18.1 84.02,87.33 ; U18.1 U18.2 ; 87.53,87.33 v3(87.53,85.62) U18.9 ; 87.53,87.33 U18.8 ; SAM_AMP_Q.3 v3(57.4,91.77) 57.4,91.03 ; SAM_AMP_Q.3 v3(57.4,93.55) 57.4,94.28 ; SAM_AMP_Q.3 60.38,92.66 ; SMA_AMP_I.3 v3(57.4,126.09) 57.4,125.35 ; SMA_AMP_I.3 v3(57.4,127.86) 57.4,128.6 ; SMA_AMP_I.3 60.38,126.97 ; 84.99,95.35 U18.4 v3(84.99,94.03) ; C43.2 95.68,127.28 ; C43.2 94.59,128.57 ; C43.2 93.4,127.28 ; 84,92.41 82.85,92.41 ; 84,92.41 U18.3 ; 84,92.41 84,93.4 ; U18.2 U18.3 ; U18.2 U18.7 ; U18.2 82.93,89.87 v3(82.93,89.84) ; U18.3 84.99,92.41 ; 88.52,87.33 88.52,86.23 ; 88.52,87.33 U18.8 ; 88.52,87.33 89.59,87.33 ; 88.39,85.57 88.39,85.57 U18.9 ; 84.02,87.33 82.8,87.33 ; 84.02,87.33 84.02,86.51 ; SAM_AMP_Q.2 v3(57.4,102.18) 57.4,102.92 ; SAM_AMP_Q.2 60.38,101.3 ; SAM_AMP_Q.2 v3(57.4,100.41) 57.4,99.67 ; U18.8 U18.7 ; U18.9 86.74,85.57 86.74,85.57 ; U18.9 87.53,84.28 ; U18.7 v3(89.54,89.87) ; U18.7 U18.6 ; v3(84.99,94.03) 85.83,94.03 ; v3(84.99,94.03) 84.99,92.41 ; v3(84.99,94.03) 84,94.03 ; U18.6 84.99,92.41 ; U18.6 88.52,92.41 ; SMA_AMP_I.2 v3(57.4,134.72) 57.4,133.99 ; SMA_AMP_I.2 60.38,135.61 ; SMA_AMP_I.2 v3(57.4,136.5) 57.4,137.24 ; 95.86,100.97 C46.2 93.04,100.97 ; 88.52,92.41 89.71,92.41 ; 88.52,92.41 88.52,93.24
  vias: v1(60.35,64.44) v1(60.35,63.4) v1(60.35,62.36) v1(61.59,64.44) v1(61.59,62.36) v1(62.84,64.44) v1(62.84,63.4) v1(62.84,62.36) v1(63.83,111.28) v1(66.17,114.05) v1(66.37,111.28) v1(69.22,120.88) v1(69.29,140.46) v1(70.18,111.28) v1(70.33,116.69) v1(71.25,122.91) v1(71.4,140.69) v1(71.45,138.15) v1(71.65,120.88) v1(72.34,121.54) v1(72.59,139.83) v1(72.69,114.12) v1(73.38,124.89) v1(73.89,114.12) v1(73.99,138.25) v1(73.99,135.71) v1(74.57,118.64) v1(74.98,117.91) v1(75.08,114.12) v1(75.13,139.45) v1(75.11,137.31) v1(76.35,133.48) v1(76.33,117.45) v1(76.48,120.09) v1(76.53,140.36) v1(76.5,138.07) v1(76.53,135.69) v1(77.22,116.99) v1(77.32,110.01) v1(77.67,140.13) v1(77.67,136.88) v1(77.67,134.72) v1(77.9,129.21) v1(77.9,127.13) v1(77.9,119.02) v1(77.95,117.93) v1(79.07,135.43) v1(79.1,140.13) v1(79.15,130.35) v1(79.12,128.32) v1(79.12,120.22) v1(79.15,118.03) v1(80.21,140.13) v1(80.21,135) v1(80.31,121.44) v1(80.31,119.05) v1(80.39,132.11) v1(80.39,129.59) v1(80.42,124.49) v1(80.72,118.39) v1(81.25,109.47) v1(81.36,124.28) v1(81.61,140.13) v1(81.61,136.4) v1(81.61,122.76) v1(81.61,120.35) v1(82.17,125.09) v1(82.75,140.13) v1(82.78,136.04) v1(83.13,111.79) v1(83.57,122.48) v1(83.62,116.89) v1(83.69,135.36) v1(83.74,127.84) v1(83.79,113.84) v1(84.91,134.11) v1(84.96,127.84) v1(86.84,140.11) v1(87.83,139.5) v1(87.83,137.03) v1(88.67,127.63) v1(88.85,132.94) v1(89.43,122.07) v1(89.48,106.2) v1(89.97,132.87) v1(90.5,139.7) v1(90.55,120.57) v1(90.55,107.67) v1(90.65,100.08) v1(90.65,96.9) v1(91.8,135.86) v1(92,124.64) v1(92.03,103.66) v1(92.18,95.38) v1(92.2,70.56) v1(92.6,115.91) v1(92.6,112.33) v1(92.79,135.69) v1(93.47,132.41) v1(93.45,127.79) v1(93.45,126.77) v1(93.45,101.07) v1(93.45,100.46) v1(93.79,115.91) v1(93.79,114.72) v1(93.79,112.2) v1(93.98,138.05) v1(94.11,120.57) v1(94.11,107.67) v1(94.21,127.79) v1(94.21,126.77) v1(94.21,101.07) v1(94.21,100.46) v1(94.98,114.72) v1(94.98,113.53) v1(94.98,112.33) v1(94.98,111.14) v1(95.15,138.05) v1(96.18,115.91) v1(96.18,114.72) v1(96.18,113.53) v1(96.18,112.33) v1(96.18,111.14) v1(96.82,135.76) v1(97.23,105.79) v1(97.37,117.11) v1(97.37,115.91) v1(97.37,114.72) v1(97.37,113.53) v1(97.37,112.33) v1(97.37,111.14) v1(97.41,103.53) v1(98.15,131.9) v1(98.56,117.11) v1(98.56,115.91) v1(98.56,114.72) v1(98.56,113.53) v1(98.56,112.33) v1(98.56,111.14) v1(98.86,62.99) v1(100.58,102.77) v1(100.51,78.23) v1(101.22,132.11) v1(101.32,79.04) v1(102.62,97.69) v1(103.63,102.77) v1(104.14,99.21) v1(105.03,132.11) v1(105.66,91.49) v1(108.84,132.11) v1(108.84,91.49) v1(111.2,91.49) v1(112.65,132.11) v2(9.14,26.06) v2(9.14,21.62) v2(9.14,15.27) v2(14.22,26.06) v2(14.86,21.62) v2(14.86,15.27) v2(19.3,26.06) v2(21.21,21.62) v2(21.21,15.27) v2(21.21,8.92) v2(21.21,5.11) v2(24.38,26.06) v2(27.56,21.62) v2(27.56,15.27) v2(27.56,8.92) v2(27.56,5.11) v2(28.83,26.06) v2(33.27,26.06) v2(33.91,15.27) v2(33.91,8.92) v2(33.91,5.11) v2(39.93,19.74) v2(40.26,53.37) v2(40.26,47.02) v2(40.26,34.32) v2(40.26,27.97) v2(40.26,15.27) v2(40.26,8.92) v2(40.26,5.11) v2(41.91,40.51) v2(43.43,26.54) v2(46.48,51.97) v2(46.61,40.67) v2(46.61,15.27) v2(46.61,8.92) v2(46.61,5.11) v2(52.96,34.32) v2(52.96,8.92) v2(52.96,5.11) v2(59.08,67.54) v2(59.31,8.92) v2(59.31,5.11) v2(64.39,8.92) v2(64.39,5.11) v2(65.02,48.92) v2(65.02,46.38) v2(65.66,34.32) v2(65.66,27.97) v2(66.55,70.21) v2(67.56,48.92) v2(68.2,46.38) v2(68.83,43.21) v2(70.74,8.92) v2(70.74,5.11) v2(71.37,43.84) v2(71.5,55.07) v2(72.01,50.19) v2(72.01,47.02) v2(72.01,40.67) v2(72.01,34.32) v2(72.01,27.97) v2(72.01,21.62) v2(73.91,52.73) v2(73.91,43.84) v2(73.91,40.67) v2(74.68,58.24) v2(75.18,50.19) v2(75.82,43.84) v2(75.82,40.67) v2(77.09,55.91) v2(77.09,8.92) v2(77.09,5.11) v2(78.36,66.7) v2(78.36,64.8) v2(78.31,62.74) v2(78.36,53.37) v2(78.36,47.02) v2(78.36,43.84) v2(78.36,40.67) v2(80.9,59.08) v2(81.53,50.19) v2(82.17,64.8) v2(82.17,57.18) v2(82.45,61.32) v2(83.44,66.07) v2(84.07,62.89) v2(84.33,64.9) v2(84.53,52.02) v2(84.71,40.67) v2(84.71,21.62) v2(84.71,15.27) v2(84.71,8.92) v2(84.71,5.11) v2(85.83,53.9) v2(85.98,67.34) v2(85.98,60.99) v2(87.33,52.17) v2(91.06,21.62) v2(91.06,15.27) v2(91.06,8.92) v2(96.37,140.41) v2(97.41,8.92) v2(98.04,81.31) v2(100.58,45.75) v2(100.84,139.8) v2(102.49,88.42) v2(103.76,45.11) v2(103.76,8.92) v2(108.51,88.42) v2(110.11,40.67) v2(110.11,34.32) v2(110.11,15.27) v2(110.11,8.92) v2(116.46,59.72) v2(116.46,53.37) v2(116.46,47.02) v2(116.46,40.67) v2(116.46,34.32) v2(116.46,27.97) v2(116.46,21.62) v2(116.46,15.27) v2(116.46,8.92) v2(122.81,66.07) v2(122.81,59.72) v2(122.81,53.37) v2(122.81,47.02) v2(122.81,40.67) v2(122.81,34.32) v2(122.81,27.97) v2(122.81,21.62) v2(122.81,15.27) v3(9.14,32.41) v3(14.22,61.29) v3(14.86,84.15) v3(14.86,76.53) v3(14.86,72.72) v3(14.86,68.91) v3(14.86,65.1) v3(18.67,84.15) v3(18.67,80.34) v3(18.67,76.53) v3(18.67,72.72) v3(18.67,68.91) v3(18.67,65.1) v3(18.67,61.93) v3(22.48,84.15) v3(22.48,80.34) v3(22.48,76.53) v3(22.48,72.72) v3(22.48,68.91) v3(22.48,65.1) v3(22.48,61.29) v3(26.29,84.15) v3(26.29,80.34) v3(26.29,76.53) v3(26.29,72.72) v3(26.29,68.91) v3(26.29,65.1) v3(26.29,61.29) v3(30.1,84.15) v3(30.1,80.34) v3(30.1,76.53) v3(30.1,72.72) v3(30.1,68.91) v3(30.1,65.1) v3(30.1,61.29) v3(33.91,84.15) v3(33.91,80.34) v3(33.91,72.72) v3(33.91,68.91) v3(33.91,65.1) v3(33.91,61.29) v3(35.18,52.73) v3(35.18,47.65) v3(35.18,42.57) v3(35.18,37.49) v3(35.18,32.41) v3(35.18,27.33) v3(37.72,84.15) v3(37.72,80.34) v3(37.72,72.72) v3(37.72,68.91) v3(37.72,65.1) v3(37.72,61.29) v3(41.53,84.15) v3(41.53,80.34) v3(41.53,72.72) v3(45.34,84.15) v3(45.34,80.34) v3(45.34,76.53) v3(49.15,84.15) v3(49.15,80.34) v3(49.63,26.37) v3(51.89,25.45) v3(51.89,24.33) v3(52.96,84.15) v3(52.96,80.34) v3(53.77,25.45) v3(53.77,24.33) v3(55.19,136.5) v3(55.19,134.72) v3(55.19,127.86) v3(55.19,126.09) v3(55.19,102.18) v3(55.19,100.41) v3(55.19,93.55) v3(55.19,91.77) v3(56.77,84.15) v3(56.77,80.34) v3(58.04,145.14) v3(58.04,141.96) v3(58.04,138.79) v3(58.04,123.8) v3(58.04,119.99) v3(58.04,112.37) v3(58.04,108.56) v3(58.04,104.75) v3(59.61,136.5) v3(59.61,134.72) v3(59.61,127.86) v3(59.61,126.09) v3(59.61,102.18) v3(59.61,100.41) v3(59.61,93.55) v3(59.61,91.77) v3(59.94,80.34) v3(60.58,84.15) v3(60.58,76.53) v3(61.21,119.99) v3(61.21,116.18) v3(61.21,112.37) v3(61.85,145.14) v3(61.85,141.96) v3(61.85,138.79) v3(61.85,135.61) v3(61.85,132.44) v3(61.85,130.15) v3(61.85,126.97) v3(61.85,123.8) v3(61.85,108.56) v3(61.85,104.75) v3(61.85,101.57) v3(61.85,98.12) v3(61.85,95.83) v3(61.85,92.66) v3(61.85,89.48) v3(63.75,84.15) v3(64.39,80.34) v3(64.39,76.53) v3(65.66,138.79) v3(65.66,135.61) v3(65.66,132.44) v3(65.66,130.15) v3(65.66,126.97) v3(65.66,108.56) v3(65.66,104.75) v3(65.66,101.57) v3(65.66,98.12) v3(65.66,95.83) v3(65.66,92.66) v3(65.66,89.48) v3(67.56,76.53) v3(68.2,84.15) v3(68.2,80.34) v3(68.2,65.1) v3(68.2,61.29) v3(68.2,57.48) v3(69.47,135.61) v3(69.47,132.44) v3(69.47,130.15) v3(69.47,98.12) v3(69.47,95.83) v3(69.47,92.66) v3(69.47,89.48) v3(71.37,109.88) v3(71.37,107.72) v3(71.37,80.34) v3(72.01,92.48) v3(72.01,84.15) v3(72.01,76.53) v3(72.01,65.1) v3(72.01,61.29) v3(73.28,133.38) v3(73.28,95.28) v3(73.28,88.93) v3(75.19,84.14) v3(75.82,80.34) v3(75.82,76.53) v3(75.82,72.72) v3(75.82,68.91) v3(75.82,65.1) v3(76.45,96.93) v3(77.09,107.72) v3(77.09,103.91) v3(77.09,92.1) v3(77.09,88.93) v3(78.99,95.28) v3(79.63,100.1) v3(79.64,84.14) v3(80.9,107.72) v3(80.9,103.91) v3(80.9,96.93) v3(80.9,92.1) v3(80.9,88.93) v3(83.01,93.78) v3(84.71,103.91) v3(84.71,100.1) v3(86,118.82) v3(86.23,96.93) v3(86.61,102.01) v3(87.02,109.32) v3(87.76,124.99) v3(87.85,103.35) v3(88.06,120.85) v3(88.52,96.93) v3(89.28,100.1) v3(89.81,126.59) v3(91.41,86.51) v3(92.33,88.49) v3(93.04,104.22) v3(93.62,89) v3(93.62,87.17) v3(94.03,86.51) v3(95.86,129.72) v3(96.24,101.22) v3(97.36,88.98) v3(97.36,87.15) v3(97.49,99.97) v3(97.66,94.54) v3(97.64,91.62) v3(99.06,87.6) v3(99.09,84.86) v3(99.19,101.6) v3(99.47,94.54) v3(99.47,91.62) v3(100.74,100.05) v3(101.65,99.14) v3(103.1,95.3) v3(103.68,93.32) v3(104.34,96.6) v3(105.66,94.89) v3(105.66,92.74) v3(108.84,94.89) v3(108.84,92.74) v3(111.2,94.89) v3(111.2,92.74) v3(117.88,81.91) v3(117.88,80.04) v3(119,81.91) v3(119,80.04)
